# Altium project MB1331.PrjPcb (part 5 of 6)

## Sheet STLink_V3E_SWD.SchDoc: ST-LINK V3 SWD Module
size A3; Date: Not used; ApprovedBy: Not used; CheckedBy: Not used; Author: Not used; CompanyName: STMicroelectronics; DrawnBy: Not used; Engineer: Not used; Organization: Not used; Address1: Not used; Address2: Not used; Address3: Not used; Address4: Not used; DocumentNumber: Not used; Revision: Not used; SheetNumber: 23; SheetTotal: 23
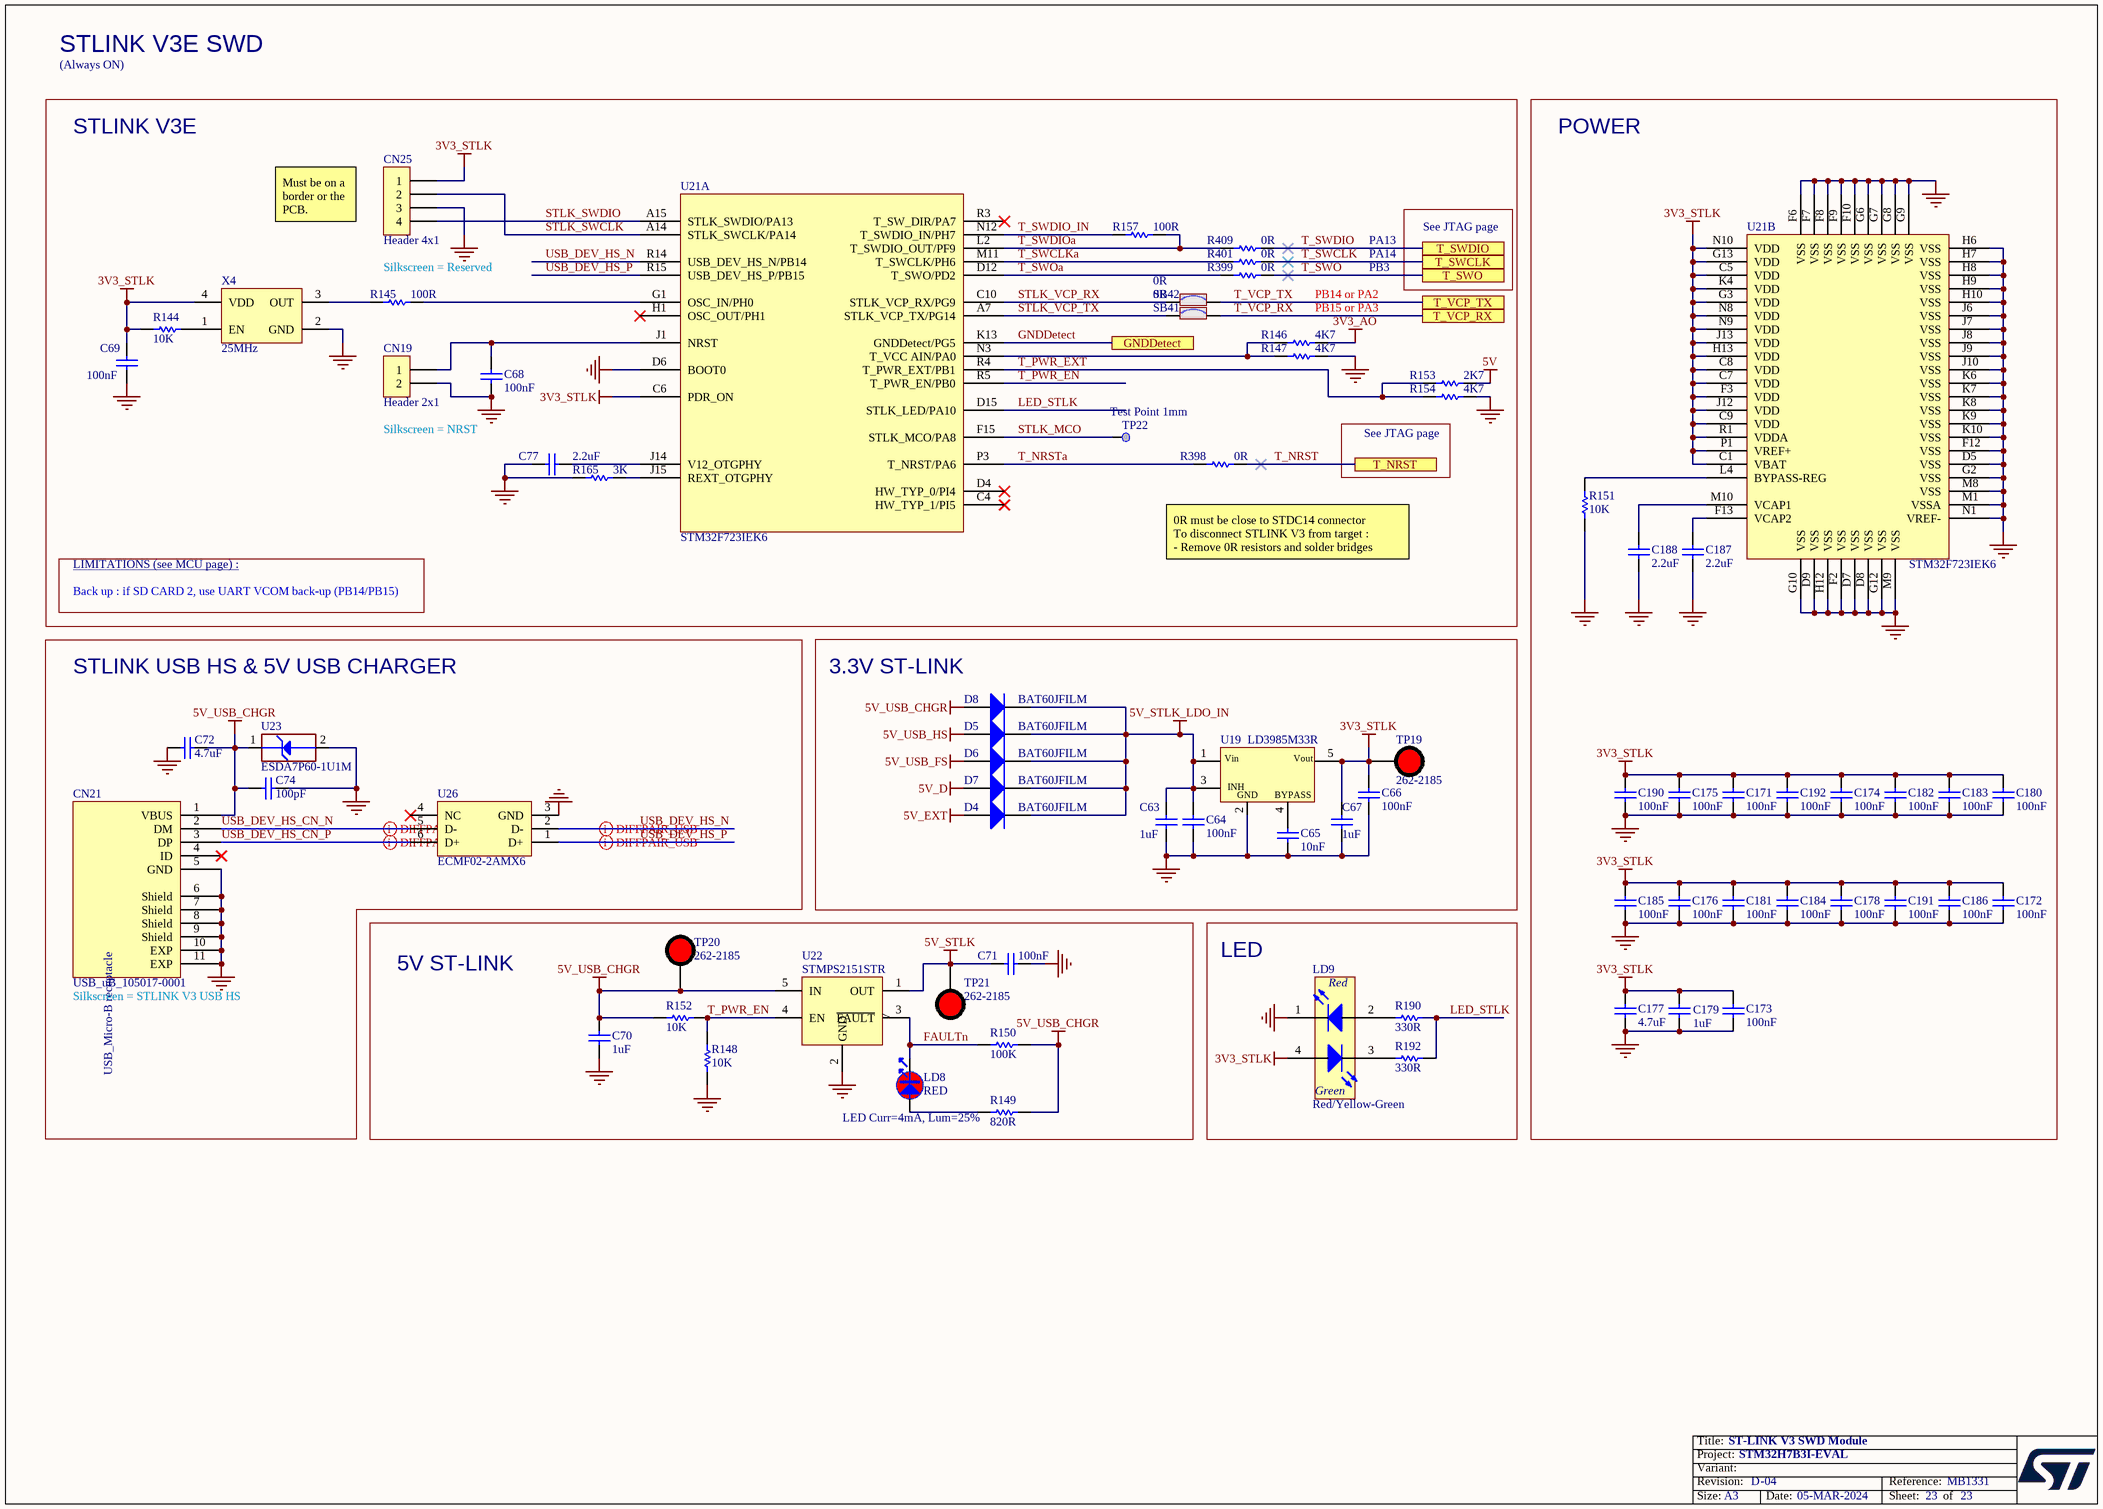
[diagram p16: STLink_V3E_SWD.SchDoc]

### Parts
C63  value 1uF  [C0603]  (hidden comment: Capacitor)
C64  value 100nF  [C0402]  (hidden comment: Capacitor)
C65  value 10nF  [C0402]  (hidden comment: Capacitor)
C66  value 100nF  [C0603]  (hidden comment: Capacitor)
C67  value 1uF  [C0603]  (hidden comment: Capacitor)
C68  value 100nF  [C0402]  (hidden comment: Capacitor)
C69  value 100nF  [C0402]  (hidden comment: Capacitor)
C70  value 1uF  [C0603]  (hidden comment: Capacitor)
C71  value 100nF  [C0402]  (hidden comment: Capacitor)
C72  value 4.7uF  [C0603]  (hidden comment: Capacitor)
C74  value 100pF  [C0402]  (hidden comment: Capacitor)
C77  value 2.2uF  [C0603]  (hidden comment: Capacitor)
C171  value 100nF  [C0402]  (hidden comment: Capacitor)
C172  value 100nF  [C0402]  (hidden comment: Capacitor)
C173  value 100nF  [C0402]  (hidden comment: Capacitor)
C174  value 100nF  [C0402]  (hidden comment: Capacitor)
C175  value 100nF  [C0402]  (hidden comment: Capacitor)
C176  value 100nF  [C0402]  (hidden comment: Capacitor)
C177  value 4.7uF  [C0603]  (hidden comment: Capacitor)
C178  value 100nF  [C0402]  (hidden comment: Capacitor)
C179  value 1uF  [C0603]  (hidden comment: Capacitor)
C180  value 100nF  [C0402]  (hidden comment: Capacitor)
C181  value 100nF  [C0402]  (hidden comment: Capacitor)
C182  value 100nF  [C0402]  (hidden comment: Capacitor)
C183  value 100nF  [C0402]  (hidden comment: Capacitor)
C184  value 100nF  [C0402]  (hidden comment: Capacitor)
C185  value 100nF  [C0402]  (hidden comment: Capacitor)
C186  value 100nF  [C0402]  (hidden comment: Capacitor)
C187  value 2.2uF  [C0603]  (hidden comment: Capacitor)
C188  value 2.2uF  [C0603]  (hidden comment: Capacitor)
C190  value 100nF  [C0402]  (hidden comment: Capacitor)
C191  value 100nF  [C0402]  (hidden comment: Capacitor)
C192  value 100nF  [C0402]  (hidden comment: Capacitor)
CN19  Header 2x1  [CON_SAMTEC_TSW-102-07-G-S]
CN21  value USB_uB_105017-0001  [CON_USBMICROB_MOLEX_105017-0001_H2P90]  (hidden comment: USB_uB_105017.0001)
CN25  Header 4x1  [CON_SAMTEC_TSW-104-07-G-S]
D4  BAT60JFILM  [DIO_SOD323]
D5  BAT60JFILM  [DIO_SOD323]
D6  BAT60JFILM  [DIO_SOD323]
D7  BAT60JFILM  [DIO_SOD323]
D8  BAT60JFILM  [DIO_SOD323]
LD8  value RED  [LED_0603_VISHAY_VLMS1300-GS08_RED_1A2K_H0P8]  (hidden comment: LED_red)
LD9  value Red/Yellow-Green  [LED_BI-GR_HSMF-A201-A00J1]  (hidden comment: LD_BICOLOR_CMS)
R144  value 10K  [R0402]  (hidden comment: Resistor)
R145  value 100R  [R0402]  (hidden comment: Resistor)
R146  value 4K7  [R0402]  (hidden comment: Resistor)
R147  value 4K7  [R0402]  (hidden comment: Resistor)
R148  value 10K  [R0402]  (hidden comment: Resistor)
R149  value 820R  [R0402]  (hidden comment: Resistor)
R150  value 100K  [R0402]  (hidden comment: Resistor)
R151  value 10K  [R0402]  (hidden comment: Resistor)
R152  value 10K  [R0402]  (hidden comment: Resistor)
R153  value 2K7  [R0402]  (hidden comment: Resistor)
R154  value 4K7  [R0402]  (hidden comment: Resistor)
R157  value 100R  [R0402]  (hidden comment: Resistor)
R165  value 3K  [R0402]  (hidden comment: Resistor)
R190  value 330R  [R0603]  (hidden comment: Resistor)
R192  value 330R  [R0603]  (hidden comment: Resistor)
R398  value 0R  [R0402]  (hidden comment: Resistor)
R399  value 0R  [R0402]  (hidden comment: Resistor)
R401  value 0R  [R0402]  (hidden comment: Resistor)
R409  value 0R  [R0402]  (hidden comment: Resistor)
SB41  value 0R  [SOLDER-BRIDGE_R0402-0R]  (hidden comment: SB_ON)
SB42  value 0R  [SOLDER-BRIDGE_R0402-0R]  (hidden comment: SB_ON)
TP19  value 262-2185  [TP_PTH-1MM_TEST-TERMINAL_RS_262-2185_RED]  (hidden comment: Test_pin_conn_red)
TP20  value 262-2185  [TP_PTH-1MM_TEST-TERMINAL_RS_262-2185_RED]  (hidden comment: Test_pin_conn_red)
TP21  value 262-2185  [TP_PTH-1MM_TEST-TERMINAL_RS_262-2185_RED]  (hidden comment: Test_pin_conn_red)
TP22  value Test Point 1mm  [TP_SMD_1MM]  (hidden comment: Test Point)  (no BOM)
U19  LD3985M33R  [REG_SOT23-5L]
U21  value STM32F723IEK6  [ICC_UFBGA201_176+25_10X10_P065]  (hidden comment: ST-LINKV3E_SWD)  (parts A,B of 2)
U22  STMPS2151STR  [MOS_SOT23-5L]
U23  value ESDA7P60-1U1M  [ESD_QFN2_1P6X1_P125]  (hidden comment: ESD-TRANSIL)
U26  ECMF02-2AMX6  [ESD_QFN-6L_1P7X1P5_P050]
X4  value 25MHz  [OSC_NDK_NZ2520SB_4P]  (hidden comment: OSCILLATOR_4_PINS)

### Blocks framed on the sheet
STLINK V3E: C68 C69 C77 CN19 CN25 R144-R147 R153 R154 R157 R165 R398 R399 R401 R409 SB41 SB42 TP22 U21 X4
POWER: C171-C188 C190-C192 R151 U21
STLINK USB HS & 5V USB CHARGER: C72 C74 CN21 U23 U26
3.3V ST-LINK: C63-C67 D4-D8 TP19 U19
5V ST-LINK: C70 C71 LD8 R148-R150 R152 TP20 TP21 U22
LED: LD9 R190 R192

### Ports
GNDDetect, T_NRST, T_SWCLK, T_SWDIO, T_SWO, T_VCP_RX, T_VCP_TX

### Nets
3V3_AO: R146.2
3V3_STLK: C66.2 C67.2 C69.2 C171.2 C172.2 C173.2 C174.2 C175.2 C176.2 C177.2 C178.2 C179.2 C180.2 C181.2 C182.2 C183.2 C184.2 C185.2 C186.2 C190.2 C191.2 C192.2 CN25.1 LD9.4(YellowGreen_anode) R144.1 TP19.1 U19.5(Vout) U21.C1(VBAT) U21.C5(VDD) U21.C6(PDR_ON) U21.C7(VDD) U21.C8(VDD) U21.C9(VDD) U21.F3(VDD) U21.G3(VDD) U21.G13(VDD) U21.H13(VDD) U21.J12(VDD) U21.J13(VDD) U21.K4(VDD) U21.N8(VDD) U21.N9(VDD) U21.N10(VDD) U21.P1(VREF+) U21.R1(VDDA) X4.4(VDD)
5V: R153.2
5V_D: D7.1(A)
5V_EXT: D4.1(A)
5V_STLK: C71.2 TP21.1 U22.1(OUT)
5V_STLK_LDO_IN: C63.1 C64.2 D4.2(K) D5.2(K) D6.2(K) D7.2(K) D8.2(K) U19.1(Vin) U19.3(CE)
5V_USB_CHGR: C70.2 C72.1 C74.1 CN21.1(VBUS) D8.1(A) R149.2 R150.2 R152.2 TP20.1 U22.5(IN) U23.1(IO1)
5V_USB_FS: D6.1(A)
5V_USB_HS: D5.1(A)
GND: C63.2 C64.1 C65.1 C66.1 C67.1 C68.1 C69.1 C70.1 C71.1 C72.2 C74.2 C77.1 C171.1 C172.1 C173.1 C174.1 C175.1 C176.1 C177.1 C178.1 C179.1 C180.1 C181.1 C182.1 C183.1 C184.1 C185.1 C186.1 C187.1 C188.1 C190.1 C191.1 C192.1 CN19.2 CN21.5(GND) CN21.6(Shield) CN21.7(Shield) CN21.8(Shield) CN21.9(Shield) CN21.10(EXP) CN21.11(EXP) CN25.3 LD9.1(RED_cathode) R147.2 R148.2 R151.1 R154.1 R165.1 U19.2(GND) U21.D5(VSS) U21.D6(BOOT0) U21.D7(VSS) U21.D8(VSS) U21.D9(VSS) U21.F2(VSS) U21.F6(VSS) U21.F7(VSS) U21.F8(VSS) U21.F9(VSS) U21.F10(VSS) U21.F12(VSS) U21.G2(VSS) U21.G6(VSS) U21.G7(VSS) U21.G8(VSS) U21.G9(VSS) U21.G10(VSS) U21.G12(VSS) U21.H6(VSS) U21.H7(VSS) U21.H8(VSS) U21.H9(VSS) U21.H10(VSS) U21.H12(VSS) U21.J6(VSS) U21.J7(VSS) U21.J8(VSS) U21.J9(VSS) U21.J10(VSS) U21.K6(VSS) U21.K7(VSS) U21.K8(VSS) U21.K9(VSS) U21.K10(VSS) U21.M1(VSSA) U21.M8(VSS) U21.M9(VSS) U21.N1(VREF-) U22.2(GND) U23.2(GND) U26.3(GND) X4.2(GND)
FAULTn: LD8.2 R150.1 U22.3(~{FAULT})
GNDDetect: U21.K13(GNDDetect/PG5) ; port GNDDetect
LED_STLK: R190.2 R192.2 U21.D15(STLK_LED/PA10)
STLK_MCO: TP22.1 U21.F15(STLK_MCO/PA8)
STLK_SWCLK: CN25.2 U21.A14(STLK_SWCLK/PA14)
STLK_SWDIO: CN25.4 U21.A15(STLK_SWDIO/PA13)
STLK_VCP_RX: SB42.1 U21.C10(STLK_VCP_RX/PG9)
STLK_VCP_TX: SB41.1 U21.A7(STLK_VCP_TX/PG14)
T_NRST: R398.2 ; port T_NRST  [project net JTAG_HOST_NRST]
T_NRSTa: R398.1 U21.P3(T_NRST/PA6)
T_PWR_EN: R148.1 R152.1 U21.R5(T_PWR_EN/PB0) U22.4(EN)
T_PWR_EXT: R153.1 R154.2 U21.R4(T_PWR_EXT/PB1)
T_SWCLK: R401.2 ; port T_SWCLK  [project net JTAG_TCK]
T_SWCLKa: R401.1 U21.M11(T_SWCLK/PH6)
T_SWDIO: R409.2 ; port T_SWDIO  [project net JTAG_TMS]
T_SWDIO_IN: R157.1 U21.N12(T_SWDIO_IN/PH7)
T_SWDIOa: R157.2 R409.1 U21.L2(T_SWDIO_OUT/PF9)
T_SWO: R399.2 ; port T_SWO  [project net JTAG_TDO]
T_SWOa: R399.1 U21.D12(T_SWO/PD2)
T_VCP_RX: SB41.2 ; port T_VCP_RX
T_VCP_TX: SB42.2 ; port T_VCP_TX
USB_DEV_HS_CN_N: CN21.2(DM) U26.5(D-)
USB_DEV_HS_CN_P: CN21.3(DP) U26.6(D+)
USB_DEV_HS_N: U21.R14(USB_DEV_HS_N/PB14) U26.2(D-)
USB_DEV_HS_P: U21.R15(USB_DEV_HS_P/PB15) U26.1(D+)
NetC65_2: C65.2 U19.4(BYPASS)
NetC68_2: C68.2 CN19.1 U21.J1(NRST)
NetC77_2: C77.2 U21.J14(V12_OTGPHY)
NetC187_2: C187.2 U21.F13(VCAP2)
NetC188_2: C188.2 U21.M10(VCAP1)
NetLD8_1: LD8.1 R149.1
NetLD9_2: LD9.2(Red_anode) R190.1
NetLD9_3: LD9.3(YellowGreen_cathode) R192.1
NetR144_2: R144.2 X4.1(EN)
NetR145_1: R145.1 X4.3(OUT)
NetR145_2: R145.2 U21.G1(OSC_IN/PH0)
NetR146_1: R146.1 R147.1 U21.N3(T_VCC_AIN/PA0)
NetR151_2: R151.2 U21.L4(BYPASS-REG)
NetR165_2: R165.2 U21.J15(REXT_OTGPHY)

Not connected (* = marked no-connect by the designer): CN21 4(ID)*; U21 C4(HW_TYP_1/PI5)* D4(HW_TYP_0/PI4)* H1(OSC_OUT/PH1)* R3(T_SW_DIR/PA7)*; U26 4(NC)*

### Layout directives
differential pair; rule Impedance Constraint [Min = 85.00    Max = 95.00    ]: USB_DEV_HS_CN_N, USB_DEV_HS_CN_P, USB_DEV_HS_N, USB_DEV_HS_P

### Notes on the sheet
- STLINK V3E SWD
- (Always ON)
- Must be on a border or the PCB.
- PA13
- See JTAG page
- Silkscreen = Reserved
- PB14 or PA2
- PB15 or PA3
- PA14
- PB3
- Silkscreen = NRST
- LIMITATIONS (see MCU page) :
- (near R398) 0R must be close to STDC14 connector
  To disconnect STLINK V3 from target :
  - Remove 0R resistors and solder bridges
- Back up : if SD CARD 2, use UART VCOM back-up (PB14/PB15)
- (near CN21) Silkscreen = STLINK V3 USB HS
- LED Curr=4mA, Lum=25%

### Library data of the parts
C63 = MCD-00238: Capacitor, MLCC, 1uF, 6V3, X5R, 10%, 0603, T=0,8mm; Manufacturer_Part_Number: CC0603KRX5R5BB105; Manufacturer: YAGEO; Part_Preference: Recommended; Provided_By: SUBCO; ECCN_US: EAR99; ECCN_EU: NEC; Component_Country_Of_Origin: China; ID: 2629; ShowFields: YES
C64 C68 C69 C71 C171-C176 C178 C180-C186 C190-C192 = MCD-00006: Capacitor, MLCC, 100nF, 16V, X7R, 10%, 0402, T=0.5mm; Manufacturer_Part_Number: CC0402KRX7R7BB104; Manufacturer: YAGEO; Alternate_Manufacturer_Part_Number: GCM155R71C104KA55D; Alternate_Manufacturer: MURATA; Part_Preference: Recommended; Partial_Alternate_Internal_Part_Number: MCD-03299; Provided_By: SUBCO; ECCN_US: EAR99; ECCN_EU: NEC; Component_Country_Of_Origin: China; ID: 2474; Order_Code_RS: 9402047; ShowFields: YES
C65 = MCD-00011: Capacitor, MLCC, 10nF, 16V, X7R, 10%, 0402, T=0.5mm; Manufacturer_Part_Number: CC0402KRX7R7BB103; Manufacturer: YAGEO; Part_Preference: Recommended; Provided_By: SUBCO; ECCN_US: EAR99; ECCN_EU: NEC; Component_Country_Of_Origin: China; ID: 2469; Order_Code_RS: 3019275; ShowFields: YES
C66 = MCD-00211: Capacitor, MLCC, 100nF, 16V, X7R, 10%, 0603, T=0,8mm; Manufacturer_Part_Number: CC0603KRX7R7BB104; Manufacturer: YAGEO; Part_Preference: Recommended; Partial_Alternate_Internal_Part_Number: MCD-01099; Provided_By: SUBCO; ECCN_US: EAR99; ECCN_EU: NEC; Component_Country_Of_Origin: China; ID: 2659; Order_Code_RS: 669-8763; ShowFields: YES
C67 C70 C179 = MCD-00010: Capacitor, MLCC, 1uF, 16V, X5R, 10%, 0603, T=0,8mm; Manufacturer_Part_Number: CC0603KRX5R7BB105; Manufacturer: YAGEO; Part_Preference: Recommended; Provided_By: SUBCO; ECCN_US: EAR99; ECCN_EU: NEC; Component_Country_Of_Origin: China; ID: 2470; Order_Code_RS: 2370680; ShowFields: YES
C72 C177 = MCD-00009: Capacitor, MLCC, 4.7uF, 16V, X5R, 10%, 0603, T=0.8mm; Manufacturer_Part_Number: CC0603KRX5R7BB475; Manufacturer: YAGEO; Part_Preference: Recommended; Partial_Alternate_Internal_Part_Number: MCD-03565; Provided_By: SUBCO; ECCN_US: EAR99; ECCN_EU: NEC; Alternate_EMS: A; Component_Country_Of_Origin: China; ID: 2471; ShowFields: YES
C74 = MCD-00205: Capacitor, MLCC, 100pF, 50V, NPO, 5%, 0402, T=0,5mm; Manufacturer_Part_Number: CC0402JRNPO9BN101; Manufacturer: YAGEO; Part_Preference: Recommended; Provided_By: SUBCO; ECCN_US: EAR99; ECCN_EU: NEC; Component_Country_Of_Origin: China; ID: 2658; ShowFields: YES
C77 C187 C188 = MCD-00012: Capacitor, MLCC, 2.2uF, 10V, X5R, 10%, 0603, T=0,8mm; Manufacturer_Part_Number: CC0603KRX5R6BB225; Manufacturer: YAGEO; Alternate_Manufacturer_Part_Number: C0603C225K8PACTU; Alternate_Manufacturer: KEMET; BMS_Part_Number: 9142010; Part_Preference: Recommended; Partial_Alternate_Internal_Part_Number: MCD-00551; Provided_By: SUBCO; ECCN_US: EAR99; ECCN_EU: NEC; Component_Country_Of_Origin: China; ID: 2467; Order_Code_RS: 2370679; ShowFields: YES
CN19 = MCD-00032: Header, 2x1, 2,54mm, VR, TH, Height 5.84mm/2.54mm; Part_Type: Connector; Manufacturer_Part_Number: TSW-102-07-G-S; Manufacturer: SAMTEC; Alternate_Manufacturer_Part_Number: 313102S111116; Alternate_Manufacturer: JIUBABA; Part_Preference: Recommended; Provided_By: SUBCO; Component_Country_Of_Origin: China, Costa Rica, Malaysia, USA, Vietnam; ID: 2484; Order_Code_RS: 2505044; ShowFields: YES
CN21 = MCD-00028: USB-MICRO-B, 0.65mm, RA, SMT, Bottom Mount,; Manufacturer_Part_Number: 1050170001; Manufacturer: MOLEX; Part_Type: Connector; Part_Preference: Recommended; Provided_By: SUBCO; Component_Country_Of_Origin: Unknown; ID: 2489; Order_Code_RS: 2293836; ShowFields: YES
CN25 = MCD-00029: Header, 4x1, 2,54mm, VR, TH, Height 5.84mm/2.54mm; Manufacturer_Part_Number: TSW-104-07-G-S; Manufacturer: SAMTEC; Part_Type: Connector; Part_Preference: Recommended; Provided_By: SUBCO; Component_Country_Of_Origin: China, Costa Rica, Malaysia, USA, Vietnam; ID: 2487; Order_Code_RS: 2667450; ShowFields: YES
D4-D8 = MCD-00034: Manufacturer: STMICROELECTRONICS; Part_Type: Diode; BMS_Part_Number: 9151097; Manufacturer_HQ_COO: EU; Part_Preference: Recommended; Provided_By: SUBCO with ST control; ECCN_US: EAR99; ECCN_EU: NEC; Component_Country_Of_Origin: China; ID: 2483; Order_Code_RS: 714-6879; ShowFields: YES
LD8 = MCD-00587: LED Red, 0603 SMD, 2V Forward Voltage; Part_Type: Display; Manufacturer_Part_Number: VLMS1300-GS08; Manufacturer: VISHAY; Alternate_Manufacturer_Part_Number: LS Q976-NR-1; Alternate_Manufacturer: OSRAM OPTO SEMICONDUCTORS; Full_Alternate_Internal_Part_Number: MCD-02401; Part_Preference: Recommended; Provided_By: SUBCO; Component_Country_Of_Origin: China; ID: 3154; ShowFields: YES
LD9 = MCD-02402: LED Bicolor, Red/Yellow-Green , 2V, 20mA, 4-PLCC; Part_Type: Display; Manufacturer_Part_Number: 67-22SURSYGC/S530-A2/TR8; Manufacturer: EVERLIGHT; Part_Preference: Not recommended; Full_Alternate_Internal_Part_Number: MCD-00051, MCD-02631; ShowFields: YES; ID: 4508
R144 R148 R151 R152 = MCD-00053: Resistor,10K,0402,1%,1/16W; Manufacturer_Part_Number: RC0402FR-0710KL; Manufacturer: YAGEO; BMS_Part_Number: 9131590; Part_Preference: Recommended; Provided_By: SUBCO; ECCN_US: EAR99; ECCN_EU: NEC; Component_Country_Of_Origin: China; ID: 2539; Order_Code_RS: 9239359; ShowFields: YES
R145 R157 = MCD-00067: Resistor,100R,0402,1%,1/16W; Manufacturer_Part_Number: RC0402FR-07100RL; Manufacturer: YAGEO; Part_Preference: Recommended; Provided_By: SUBCO; ECCN_US: EAR99; ECCN_EU: NEC; Component_Country_Of_Origin: China; ID: 2527; Order_Code_RS: 9239111; ShowFields: YES
R146 R147 R154 = MCD-00065: Resistor,4K7,0402,1%,1/16W; Manufacturer_Part_Number: RC0402FR-074K7L; Manufacturer: YAGEO; Alternate_Manufacturer_Part_Number: RT0402FRE074K7L; Part_Preference: Recommended; Partial_Alternate_Internal_Part_Number: MCD-03300; Provided_By: SUBCO; ECCN_US: EAR99; ECCN_EU: NEC; Component_Country_Of_Origin: China; ID: 2526; Order_Code_RS: 9239316; ShowFields: YES
R149 = MCD-00527: Resistor,820R,0402,1%,1/16W; Manufacturer_Part_Number: RC0402FR-07820RL; Manufacturer: YAGEO; Part_Preference: Recommended; Provided_By: SUBCO; ECCN_US: EAR99; ECCN_EU: NEC; Component_Country_Of_Origin: China; ID: 3217; ShowFields: YES
R150 = MCD-00059: Resistor,100K,0402,1%,1/16W; Manufacturer_Part_Number: RC0402FR-07100KL; Manufacturer: YAGEO; Alternate_Manufacturer_Part_Number: RT0402FRE07100KL; Part_Preference: Recommended; Partial_Alternate_Internal_Part_Number: MCD-03301; Provided_By: SUBCO; ECCN_US: EAR99; ECCN_EU: NEC; Component_Country_Of_Origin: China; ID: 2533; Order_Code_RS: 2421891; ShowFields: YES
R153 = MCD-00055: Resistor,2K7,0402,1%,1/16W; Manufacturer_Part_Number: RC0402FR-072K7L; Manufacturer: YAGEO; Part_Preference: Recommended; Provided_By: SUBCO; ECCN_US: EAR99; ECCN_EU: NEC; Component_Country_Of_Origin: China; ID: 2535; Order_Code_RS: 9239286; ShowFields: YES
R165 = MCD-00185: Resistor,3K,0402,1%,1/16W; Manufacturer_Part_Number: RC0402FR-073KL; Manufacturer: YAGEO; Part_Preference: Recommended; Provided_By: SUBCO; ECCN_US: EAR99; ECCN_EU: NEC; Component_Country_Of_Origin: China; ID: 2682; ShowFields: YES
R190 R192 = MCD-00197: Resistor,330R,0603,1%,1/10W; Manufacturer_Part_Number: RC0603FR-07330RL; Manufacturer: YAGEO; BMS_Part_Number: 9129729; Part_Preference: Recommended; Provided_By: SUBCO; ECCN_US: EAR99; ECCN_EU: NEC; Component_Country_Of_Origin: China; ID: 2672; ShowFields: YES
R398 R399 R401 R409 = MCD-00052: Resistor,0R,0402,5%,1/16W; Manufacturer_Part_Number: RC0402JR-070RL; Manufacturer: YAGEO; Part_Preference: Recommended; Provided_By: SUBCO; ECCN_US: EAR99; ECCN_EU: NEC; Component_Country_Of_Origin: China; ID: 2540; Order_Code_RS: 9232516RL; ShowFields: YES
SB41 SB42 = MCD-01618: Solder Bridge 0402 ON; Part_Type: Resistor; Manufacturer_Part_Number: RC0402JR-070RL; Manufacturer: YAGEO; Part_Preference: Recommended; Provided_By: SUBCO; Component_Country_Of_Origin: China; ID: 3718; Order_Code_RS: 618-5804; ShowFields: YES
TP19-TP21 = MCD-00712: RS Pro 1mm Red Test Terminal; Part_Type: Misc; Manufacturer: RS PRO; Part_Preference: Recommended; Provided_By: SUBCO; Component_Country_Of_Origin: UK; ID: 3035; ShowFields: YES
TP22 = MCD-00074: Test Point 1mm; Part_Type: Misc; Part_Preference: Recommended; Component_Country_Of_Origin: Unknown; ID: 2518; ShowFields: YES
U19 = MCD-00086: Ultra low drop-low noise BiCMOS voltage, regulators low ESR capacitors compatible; Manufacturer: STMICROELECTRONICS; Part_Type: IC; BMS_Part_Number: 9176161; Manufacturer_HQ_COO: EU; Part_Preference: Recommended; Provided_By: SUBCO with ST control; ECCN_US: EAR99; ECCN_EU: NEC; Component_Country_Of_Origin: China; ID: 2506; Order_Code_RS: 168-6500; ShowFields: YES
U21 = MCD-00596: STM32F723IEK  (STM32F7) BGA176; Part_Type: IC; Manufacturer: STMICROELECTRONICS; BMS_Part_Number: 9175300; Manufacturer_HQ_COO: EU; Part_Preference: Recommended; Provided_By: SUBCO with ST control; ECCN_US: 3A991A2; ECCN_EU: NEC; Component_Country_Of_Origin: Philippines; ID: 3144; Order_Code_RS: 135-8268; ShowFields: YES
U22 = MCD-00159: 500mA, Enhanced single channel power switches with active high enable pin; Part_Type: IC; Manufacturer: STMICROELECTRONICS; Alternate_Manufacturer_Part_Number: TPS2051C; Alternate_Manufacturer: TEXAS INSTRUMENTS; BMS_Part_Number: 9159009; Part_Preference: Recommended; Provided_By: SUBCO with ST control; ECCN_US: EAR99; ECCN_EU: NEC; Component_Country_Of_Origin: Malaysia; ID: 2708; Order_Code_RS: 165-5516; ShowFields: YES
U23 = MCD-00251: High power transient voltage suppressor, 7V breakdown; Part_Type: Diode; Manufacturer: STMICROELECTRONICS; BMS_Part_Number: 9179042; Manufacturer_HQ_COO: EU; Part_Preference: Recommended; Provided_By: SUBCO with ST control; ECCN_US: EAR99; ECCN_EU: NEC; Component_Country_Of_Origin: China; ID: 2618; Order_Code_RS: 110-6381; ShowFields: YES
U26 = MCD-00649: Common mode filter with ESD protection for USB 2.0 interface; Part_Type: Diode; Manufacturer: STMICROELECTRONICS; BMS_Part_Number: 9151138; Manufacturer_HQ_COO: EU; Part_Preference: Recommended; Provided_By: SUBCO with ST control; ECCN_US: EAR99; ECCN_EU: NEC; Component_Country_Of_Origin: China; ID: 3094; Order_Code_RS: 880-5276; ShowFields: YES
X4 = MCD-00597: Oscillator 25Mhz, +-50ppm, Vcc:3.3V typ, square wave: [0.1Vcc;0.9Vcc], Enable pin, SMD; Part_Type: Crystal_Osc; Manufacturer_Part_Number: NZ2520SH-25MHZ-END4869C; Manufacturer: NDK; Alternate_Manufacturer_Part_Number: NZ2520SB 25MHz END4869B; BMS_Part_Number: 9157050; Part_Preference: Recommended; Provided_By: SUBCO; ECCN_US: EAR99; ECCN_EU: NEC; Component_Country_Of_Origin: Unknown; ID: 3148; ShowFields: YES

## Sheet ExtensionConnector.SchDoc: Extension Connectors
size A4; Date: Not used; ApprovedBy: Not used; CheckedBy: Not used; Author: Not used; CompanyName: STMicroelectronics; DrawnBy: Not used; Engineer: Not used; Organization: Not used; Address1: Not used; Address2: Not used; Address3: Not used; Address4: Not used; DocumentNumber: Not used; Revision: Not used; SheetNumber: 19; SheetTotal: 23
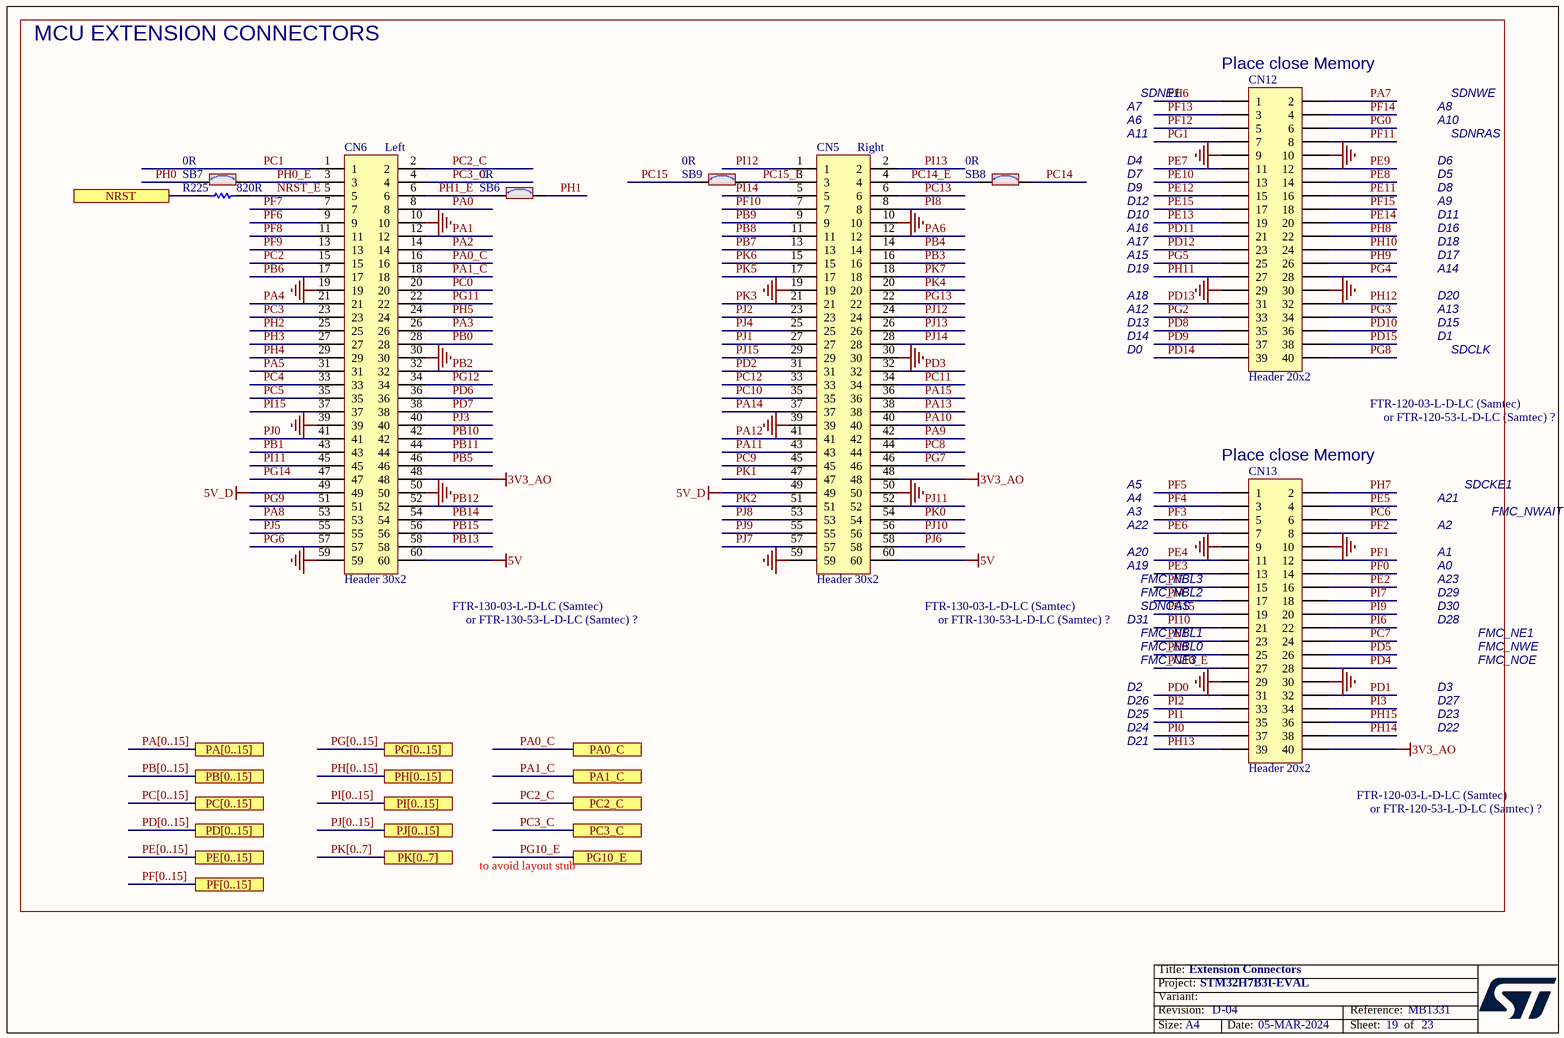
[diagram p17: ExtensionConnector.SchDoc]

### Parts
CN5  Header 30x2  [CON_SAMTEC_FTR-130-53-L-D-LC]
CN6  Header 30x2  [CON_SAMTEC_FTR-130-53-L-D-LC]
CN12  Header 20x2  [CON_SAMTEC_FTR-120-53-L-D-LC]
CN13  Header 20x2  [CON_SAMTEC_FTR-120-53-L-D-LC]
R225  value 820R  [R0603]  (hidden comment: Resistor)
SB6  value 0R  [SOLDER-BRIDGE_R0603-0R]  (hidden comment: SB_ON)
SB7  value 0R  [SOLDER-BRIDGE_R0603-0R]  (hidden comment: SB_ON)
SB8  value 0R  [SOLDER-BRIDGE_R0603-0R]  (hidden comment: SB_ON)
SB9  value 0R  [SOLDER-BRIDGE_R0603-0R]  (hidden comment: SB_ON)

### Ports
NRST, PA0_C, PA1_C, PA[0..15], PB[0..15], PC2_C, PC3_C, PC[0..15], PD[0..15], PE[0..15], PF[0..15], PG10_E, PG[0..15], PH[0..15], PI[0..15], PJ[0..15], PK[0..7]

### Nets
3V3_AO: CN5.48 CN6.48 CN13.40
5V: CN5.60 CN6.60
5V_D: CN5.49 CN6.49
GND: CN5.10 CN5.19 CN5.30 CN5.39 CN5.50 CN5.59 CN6.10 CN6.19 CN6.30 CN6.39 CN6.50 CN6.59 CN12.9 CN12.10 CN12.29 CN12.30 CN13.9 CN13.10 CN13.29 CN13.30
NRST: R225.1 ; port NRST
NRST_E: CN6.5 R225.2
PA0: CN6.8
PA0_C: CN6.16 ; port PA0_C
PA1: CN6.12
PA1_C: CN6.18 ; port PA1_C
PA2: CN6.14
PA3: CN6.26
PA4: CN6.21
PA5: CN6.31
PA6: CN5.12
PA7: CN12.2
PA8: CN6.53
PA9: CN5.42
PA10: CN5.40
PA11: CN5.43
PA12: CN5.41
PA13: CN5.38
PA14: CN5.37
PA15: CN5.36
PB0: CN6.28
PB1: CN6.43
PB2: CN6.32
PB3: CN5.16
PB4: CN5.14
PB5: CN6.46
PB6: CN6.17  [project net DFSDM1_DATIN5]
PB7: CN5.13
PB8: CN5.11
PB9: CN5.9
PB10: CN6.42
PB11: CN6.44
PB12: CN6.52
PB13: CN6.58
PB14: CN6.54
PB15: CN6.56
PC0: CN6.20
PC1: CN6.1
PC2: CN6.15
PC2_C: CN6.2 ; port PC2_C
PC3: CN6.23
PC3_C: CN6.4 ; port PC3_C
PC4: CN6.33
PC5: CN6.35
PC6: CN13.6
PC7: CN13.24
PC8: CN5.44
PC9: CN5.45
PC10: CN5.35
PC11: CN5.34
PC12: CN5.33
PC13: CN5.6
PC14: SB8.2
PC14_E: CN5.4 SB8.1
PC15: SB9.1
PC15_E: CN5.3 SB9.2
PD0: CN13.31
PD1: CN13.32
PD2: CN5.31
PD3: CN5.32
PD4: CN13.28
PD5: CN13.26
PD6: CN6.36
PD7: CN6.38
PD8: CN12.35
PD9: CN12.37
PD10: CN12.36
PD11: CN12.21
PD12: CN12.23
PD13: CN12.31
PD14: CN12.39
PD15: CN12.38
PE0: CN13.25
PE1: CN13.23
PE2: CN13.16
PE3: CN13.13
PE4: CN13.11
PE5: CN13.4
PE6: CN13.7
PE7: CN12.11
PE8: CN12.14
PE9: CN12.12
PE10: CN12.13
PE11: CN12.16
PE12: CN12.15
PE13: CN12.19
PE14: CN12.20
PE15: CN12.17
PF0: CN13.14
PF1: CN13.12
PF2: CN13.8
PF3: CN13.5
PF4: CN13.3
PF5: CN13.1
PF6: CN6.9
PF7: CN6.7
PF8: CN6.11
PF9: CN6.13
PF10: CN5.7
PF11: CN12.8
PF12: CN12.5
PF13: CN12.3
PF14: CN12.4
PF15: CN12.18
PG0: CN12.6
PG1: CN12.7
PG2: CN12.33
PG3: CN12.34
PG4: CN12.28
PG5: CN12.25
PG6: CN6.57
PG7: CN5.46
PG8: CN12.40
PG9: CN6.51
PG10_E: CN13.27 ; port PG10_E
PG11: CN6.22
PG12: CN6.34
PG13: CN5.22
PG14: CN6.47
PG15: CN13.19
PH0: SB7.1
PH0_E: CN6.3 SB7.2
PH1: SB6.2
PH1_E: CN6.6 SB6.1
PH2: CN6.25  [project net CTP_INT]
PH3: CN6.27
PH4: CN6.29
PH5: CN6.24
PH6: CN12.1
PH7: CN13.2
PH8: CN12.22
PH9: CN12.26
PH10: CN12.24
PH11: CN12.27
PH12: CN12.32
PH13: CN13.39
PH14: CN13.38
PH15: CN13.36
PI0: CN13.37
PI1: CN13.35
PI2: CN13.33
PI3: CN13.34
PI4: CN13.17
PI5: CN13.15
PI6: CN13.22
PI7: CN13.18
PI8: CN5.8
PI9: CN13.20
PI10: CN13.21
PI11: CN6.45
PI12: CN5.1
PI13: CN5.2
PI14: CN5.5
PI15: CN6.37
PJ0: CN6.41
PJ1: CN5.27
PJ2: CN5.23
PJ3: CN6.40
PJ4: CN5.25
PJ5: CN6.55
PJ6: CN5.58
PJ7: CN5.57
PJ8: CN5.53
PJ9: CN5.55
PJ10: CN5.56
PJ11: CN5.52
PJ12: CN5.24
PJ13: CN5.26
PJ14: CN5.28
PJ15: CN5.29
PK0: CN5.54
PK1: CN5.47
PK2: CN5.51
PK3: CN5.21
PK4: CN5.20
PK5: CN5.17
PK6: CN5.15
PK7: CN5.18

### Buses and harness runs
bus PA[0..15] = port PA[0..15]
bus PB[0..15] = port PB[0..15]
bus PC[0..15] = port PC[0..15]
bus PD[0..15] = port PD[0..15]
bus PE[0..15] = port PE[0..15]
bus PF[0..15] = port PF[0..15]
bus PG[0..15] = port PG[0..15]
bus PH[0..15] = port PH[0..15]
bus PI[0..15] = port PI[0..15]
bus PJ[0..15] = port PJ[0..15]
bus PK[0..7] = port PK[0..7]

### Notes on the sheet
- MCU EXTENSION CONNECTORS
- A7
- SDNE1
- (near CN12) Place close Memory
- A8
- SDNWE
- (near CN6) Left
- (near CN5) Right
- D4
- D7
- A6
- A11
- D5
- D6
- A10
- SDNRAS
- A16
- A17
- D9
- D10
- D12
- D8
- D11
- A9
- D16
- D18
- A18
- A12
- A15
- D19
- A13
- A14
- D17
- D20
- D13
- D14
- D0
- D15
- D1
- SDCLK
- (near CN12) FTR-120-03-L-D-LC (Samtec)
- or FTR-120-53-L-D-LC (Samtec) ?
- A3
- A4
- A5
- (near CN13) Place close Memory
- A21
- SDCKE1
- FMC_NWAIT
- A19
- A20
- A22
- FMC_NBL3
- A23
- A0
- A1
- A2
- (near CN6) FTR-130-03-L-D-LC (Samtec)
- or FTR-130-53-L-D-LC (Samtec) ?
- (near CN5) FTR-130-03-L-D-LC (Samtec)
- D31
- FMC_NBL0
- FMC_NBL1
- SDNCAS
- FMC_NBL2
- D28
- D29
- D30
- FMC_NWE
- FMC_NE1
- D2
- D25
- D26
- FMC_NE3
- D3
- D23
- D27
- FMC_NOE
- D21
- D24
- D22
- (near CN13) FTR-120-03-L-D-LC (Samtec)
- to avoid layout stub

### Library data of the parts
CN5 CN6 = MCD-00576: Header 30x2, 1.27mm, VR, CMS, Height 7.24mm; Part_Type: Connector; Manufacturer_Part_Number: FTR-130-53-L-D-LC; Manufacturer: SAMTEC; Alternate_Manufacturer_Part_Number: P1039-2*30MGF-089-1A; Alternate_Manufacturer: JIUBABA; Part_Preference: Recommended; Provided_By: SUBCO; Component_Country_Of_Origin: China, Costa Rica, Malaysia, USA, Vietnam; ID: 3170; ShowFields: YES
CN12 CN13 = MCD-00578: Header 20x2, 1.27mm, VR, CMS, Height 7.24mm; Part_Type: Connector; Manufacturer_Part_Number: FTR-120-53-L-D-LC; Manufacturer: SAMTEC; Alternate_Manufacturer_Part_Number: P1039-2*20MGF-089-1A; Alternate_Manufacturer: JIUBABA; Part_Preference: Recommended; Provided_By: SUBCO; Component_Country_Of_Origin: China, Costa Rica, Malaysia, USA, Vietnam; ID: 3165; ShowFields: YES
R225 = MCD-00528: Resistor,820R,0603,1%,1/10W; Manufacturer_Part_Number: RC0603FR-07820RL; Manufacturer: YAGEO; BMS_Part_Number: 9129759; Part_Preference: Recommended; Provided_By: SUBCO; ECCN_US: EAR99; ECCN_EU: NEC; Component_Country_Of_Origin: China; ID: 3218; ShowFields: YES
SB6-SB9 = MCD-00071: Solder Bridge ON; Part_Type: Resistor; Manufacturer_Part_Number: RC0603JR-070RL; Manufacturer: YAGEO; Manufacturer_HQ_COO: Unknown; Part_Preference: Recommended; Provided_By: SUBCO; Component_Country_Of_Origin: China; ID: 2521; Order_Code_RS: 199-5647; ShowFields: YES

## Sheet USB_OTG_FS.SchDoc: USB_OTG_FS
size A4; Date: Not used; ApprovedBy: Not used; CheckedBy: Not used; Author: Not used; CompanyName: STMicroelectronics; DrawnBy: Not used; Engineer: Not used; Organization: Not used; Address1: Not used; Address2: Not used; Address3: Not used; Address4: Not used; DocumentNumber: Not used; Revision: Not used; SheetNumber: 5; SheetTotal: 23
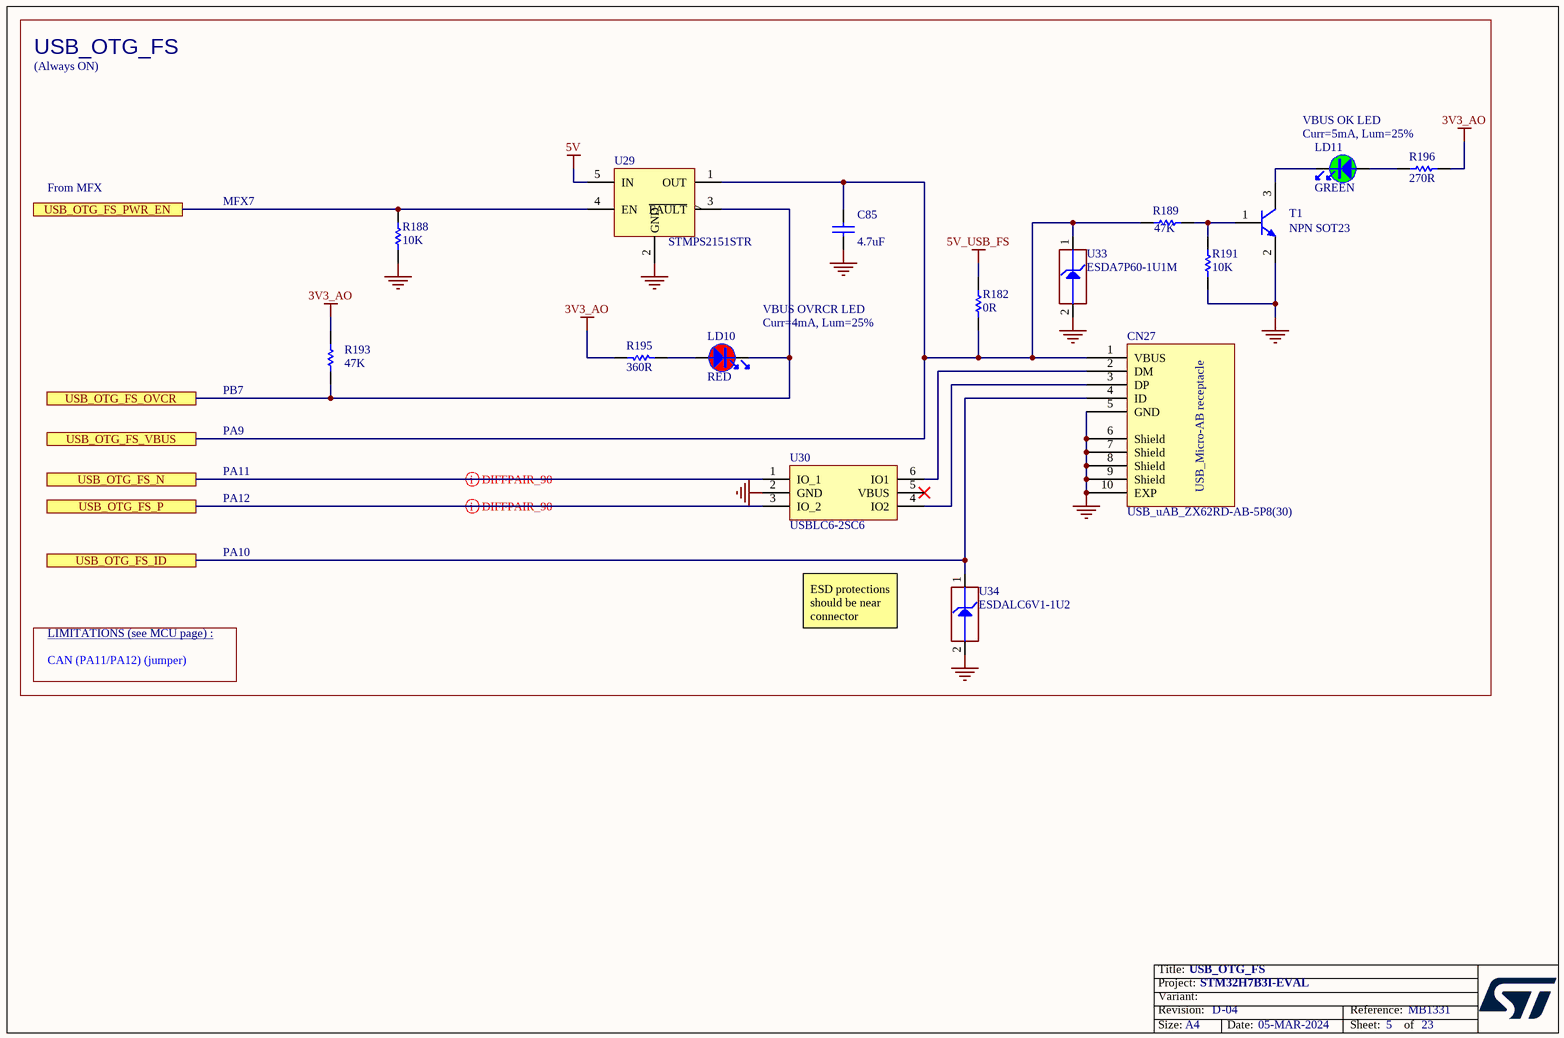
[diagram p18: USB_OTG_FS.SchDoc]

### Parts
C85  value 4.7uF  [C0603]  (hidden comment: Capacitor)
CN27  value USB_uAB_ZX62RD-AB-5P8(30)  [CON_USBMICROAB_MOLEX_47590-0001_H3]  (hidden comment: USB_uAB_47590.0001)
LD10  value RED  [LED_0603_VISHAY_VLMS1300-GS08_RED_1A2K_H0P8]  (hidden comment: LED_red)
LD11  value GREEN  [LED_0603_OSRAM_LG-Q396-PS-35_GREEN_1A2K_H0P4]  (hidden comment: LED_green)
R182  value 0R  [R0805]  (hidden comment: Resistor)
R188  value 10K  [R0402]  (hidden comment: Resistor)
R189  value 47K  [R0402]  (hidden comment: Resistor)
R191  value 10K  [R0402]  (hidden comment: Resistor)
R193  value 47K  [R0402]  (hidden comment: Resistor)
R195  value 360R  [R0402]  (hidden comment: Resistor)
R196  value 270R  [R0402]  (hidden comment: Resistor)
T1  value NPN SOT23  [NPN_SOT23]  (hidden comment: 9013-SOT23)
U29  STMPS2151STR  [MOS_SOT23-5L]
U30  USBLC6-2SC6  [ESD_SOT23-6L]
U33  value ESDA7P60-1U1M  [ESD_QFN2_1P6X1_P125]  (hidden comment: ESD-TRANSIL)
U34  value ESDALC6V1-1U2  [ESD_ST0201]  (hidden comment: ESD-TRANSIL)

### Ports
USB_OTG_FS_ID, USB_OTG_FS_N, USB_OTG_FS_OVCR, USB_OTG_FS_P, USB_OTG_FS_PWR_EN, USB_OTG_FS_VBUS

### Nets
3V3_AO: R193.2 R195.2 R196.2
5V: U29.5(IN)
5V_USB_FS: R182.2
GND: C85.1 CN27.5(GND) CN27.6(Shield) CN27.7(Shield) CN27.8(Shield) CN27.9(Shield) CN27.10(EXP) R188.2 R191.1 T1.2(E) U29.2(GND) U30.2(GND) U33.2(GND) U34.2(GND)
USB_OTG_FS_ID: CN27.4(ID) U34.1(IO1) ; port USB_OTG_FS_ID
USB_OTG_FS_N: U30.1(IO_1) ; port USB_OTG_FS_N
USB_OTG_FS_OVCR: LD10.2 R193.1 U29.3(~{FAULT}) ; port USB_OTG_FS_OVCR
USB_OTG_FS_P: U30.3(IO_2) ; port USB_OTG_FS_P
USB_OTG_FS_PWR_EN: R188.1 U29.4(EN) ; port USB_OTG_FS_PWR_EN
USB_OTG_FS_VBUS: C85.2 CN27.1(VBUS) R182.1 R189.1 U29.1(OUT) U33.1(IO1) ; port USB_OTG_FS_VBUS
NetCN27_2: CN27.2(DM) U30.6(IO1)
NetCN27_3: CN27.3(DP) U30.4(IO2)
NetLD10_1: LD10.1 R195.1
NetLD11_1: LD11.1 R196.1
NetLD11_2: LD11.2 T1.3(C)
NetR189_2: R189.2 R191.2 T1.1(B)

Not connected (* = marked no-connect by the designer): U30 5(VBUS)*

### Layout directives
differential pair: USB_OTG_FS_N, USB_OTG_FS_P

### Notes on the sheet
- USB_OTG_FS
- (Always ON)
- VBUS OK LED
- Curr=5mA, Lum=25%
- From MFX
- MFX7
- VBUS OVRCR LED
- Curr=4mA, Lum=25%
- PA9
- PB7
- PA11
- PA12
- PA10
- LIMITATIONS (see MCU page) :
- ESD protections should be near connector
- CAN (PA11/PA12) (jumper)

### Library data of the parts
C85 = MCD-00009: as C72 on sheet STLink_V3E_SWD
CN27 = MCD-00661: USB-MICRO-AB Receptacle, RA, SMT + DIP, Standard, Top Mount, USB certified (symbol & footprint compatible with MCD-00022); Part_Type: Connector; Manufacturer_Part_Number: ZX62RD-AB-5P8(30); Manufacturer: HIROSE; Part_Preference: Recommended; Provided_By: SUBCO; Component_Country_Of_Origin: Japan; ID: 3083; Order_Code_RS: 136-1404; ShowFields: YES
LD10 = MCD-00587: as LD8 on sheet STLink_V3E_SWD
LD11 = MCD-00588: LED Green, 0603 SMD, Forward Voltage Typ=2V, Max=2.5V; Part_Type: Display; Manufacturer_Part_Number: LG Q396-PS-35; Manufacturer: OSRAM OPTO SEMICONDUCTORS; Alternate_Manufacturer_Part_Number: VLMTG1300-GS08; Alternate_Manufacturer: VISHAY SEMICONDUCTOR OPTO DIVISION; Part_Preference: Recommended; Partial_Alternate_Internal_Part_Number: MCD-02400, MCD-03155; Provided_By: SUBCO; Component_Country_Of_Origin: Unknown; ID: 3155; ShowFields: YES
R182 = MCD-00179: Resistor,0R,0805,5%; Manufacturer_Part_Number: RC0805JR-070RL; Manufacturer: YAGEO; Part_Preference: Recommended; Provided_By: SUBCO; ECCN_US: EAR99; ECCN_EU: NEC; Component_Country_Of_Origin: China; ID: 2685; ShowFields: YES
R188 R191 = MCD-00053: as R144 on sheet STLink_V3E_SWD
R189 R193 = MCD-00063: Resistor,47K,0402,1%,1/16W; Manufacturer_Part_Number: RC0402FR-0747KL; Manufacturer: YAGEO; Part_Preference: Recommended; Provided_By: SUBCO; ECCN_US: EAR99; ECCN_EU: NEC; Component_Country_Of_Origin: China; ID: 2528; Order_Code_RS: 9239430; ShowFields: YES
R195 = MCD-00461: Resistor,360R,0402,1%,1/16W; Manufacturer_Part_Number: RC0402FR-07360RL; Manufacturer: YAGEO; Part_Preference: Recommended; Provided_By: SUBCO; ECCN_US: EAR99; ECCN_EU: NEC; Component_Country_Of_Origin: China; ID: 2816; ShowFields: YES
R196 = MCD-00441: Resistor,270R,0402,1%,1/16W; Manufacturer_Part_Number: RC0402FR-07270RL; Manufacturer: YAGEO; Part_Preference: Recommended; Provided_By: SUBCO; ECCN_US: EAR99; ECCN_EU: NEC; Component_Country_Of_Origin: China; ID: 2838; ShowFields: YES
T1 = MCD-00073: NPN Bipolar Transistor; Manufacturer_Part_Number: BSR14; Manufacturer: ON SEMICONDUCTOR; Part_Type: IC; Alternate_Manufacturer_Part_Number: MMBT2222LT1G / MMBT2222ALT1G / MMBT2222ALT3G; Part_Preference: Recommended; Partial_Alternate_Internal_Part_Number: MCD-01737, MCD-03305, , MCD-02988; Provided_By: SUBCO; ECCN_US: EAR99; ECCN_EU: NEC; Component_Country_Of_Origin: Unknown; ID: 2519; ShowFields: YES
U29 = MCD-00159: 500mA, Enhanced single channel power switches with active high enable pin; Manufacturer: STMICROELECTRONICS; Part_Type: IC; Alternate_Manufacturer_Part_Number: TPS2051C; Alternate_Manufacturer: TEXAS INSTRUMENTS; BMS_Part_Number: 9159009; Part_Preference: Recommended; Provided_By: SUBCO with ST control; ECCN_US: EAR99; ECCN_EU: NEC; Component_Country_Of_Origin: Malaysia; ID: 2708; Order_Code_RS: 165-5516; ShowFields: YES
U30 = MCD-00163: Very low capacitance ESD protection; Part_Type: Diode; Manufacturer: STMICROELECTRONICS; BMS_Part_Number: 9151075; Part_Preference: Recommended; Provided_By: SUBCO with ST control; ECCN_US: EAR99; ECCN_EU: NEC; Component_Country_Of_Origin: China; ID: 2707; Order_Code_RS: 920-6266; ShowFields: YES
U33 = MCD-00251: as U23 on sheet STLink_V3E_SWD
U34 = MCD-00170: ESD protection 6V1; Part_Type: Diode; Manufacturer: STMICROELECTRONICS; BMS_Part_Number: 9151132; Manufacturer_HQ_COO: EU; Part_Preference: Recommended; Provided_By: SUBCO with ST control; ECCN_US: EAR99; ECCN_EU: NEC; Component_Country_Of_Origin: China; ID: 2696; Order_Code_RS: 795-8404; ShowFields: YES

## Sheet USB_OTG_HS_externalPHY.SchDoc: USB OTG HS with external PHY
size A4; Date: Not used; ApprovedBy: Not used; CheckedBy: Not used; Author: Not used; CompanyName: STMicroelectronics; DrawnBy: Not used; Engineer: Not used; Organization: Not used; Address1: Not used; Address2: Not used; Address3: Not used; Address4: Not used; DocumentNumber: Not used; Revision: Not used; SheetNumber: 6; SheetTotal: 23
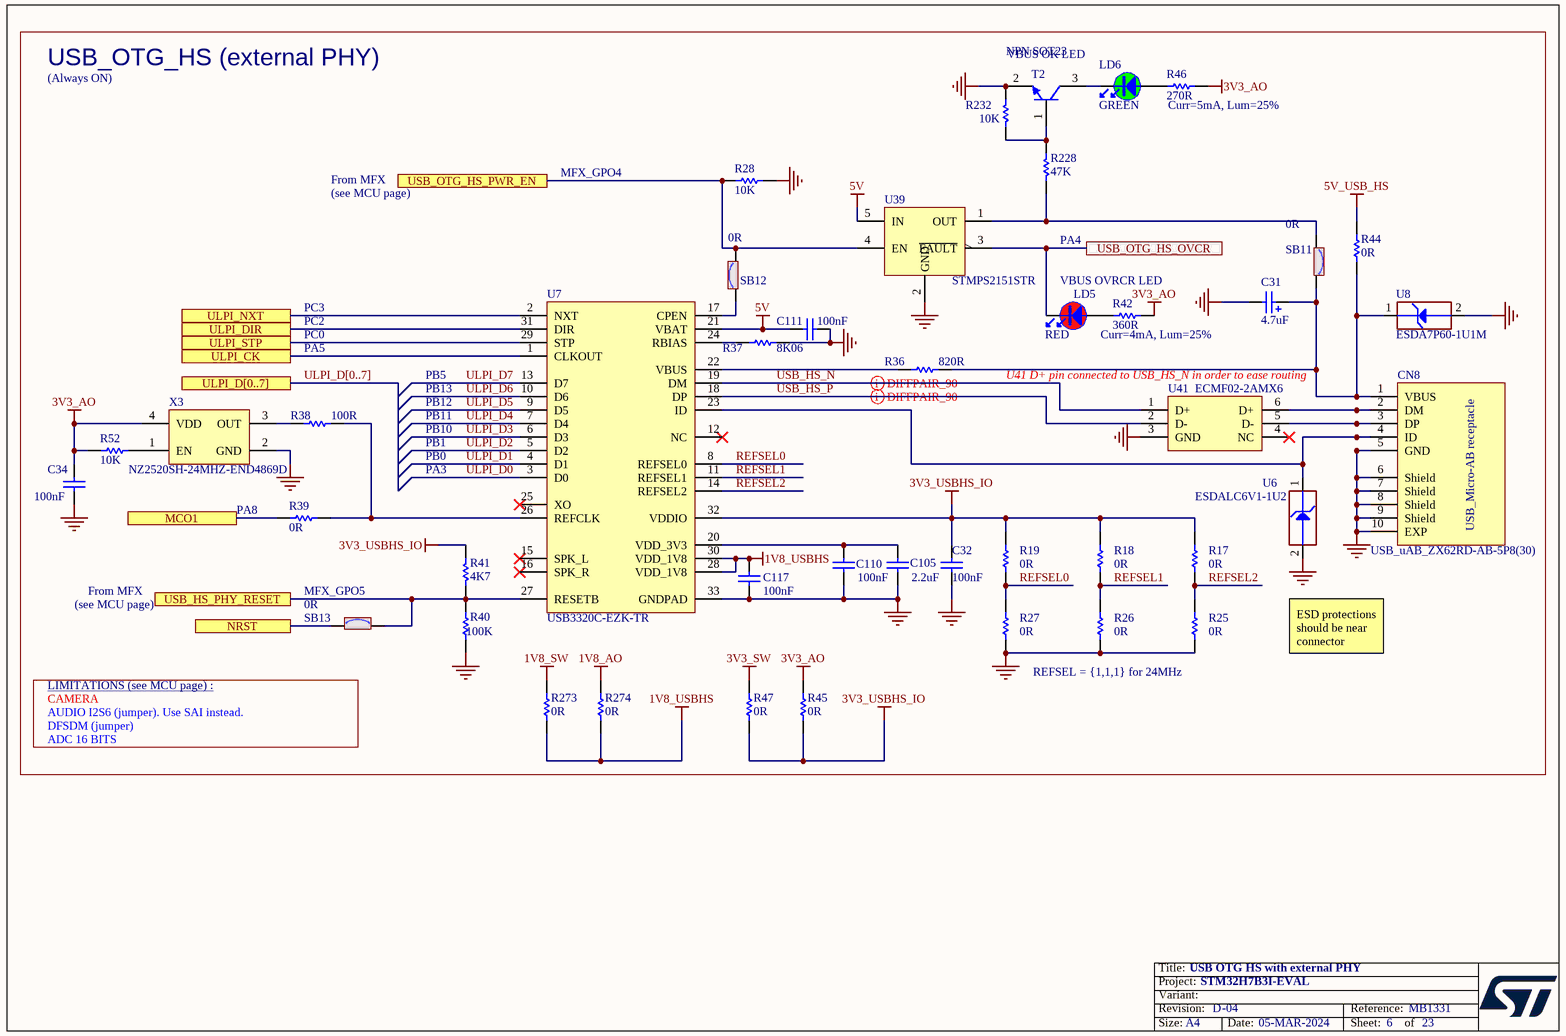
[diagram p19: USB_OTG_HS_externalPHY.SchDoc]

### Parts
C31  value 4.7uF  [CPOL_TAJ-A_1206_H180]  (hidden comment: Cap_POL_TANA)
C32  value 100nF  [C0402]  (hidden comment: Capacitor)
C34  value 100nF  [C0402]  (hidden comment: Capacitor)
C105  value 2.2uF  [C0603]  (hidden comment: Capacitor)
C110  value 100nF  [C0402]  (hidden comment: Capacitor)
C111  value 100nF  [C0402]  (hidden comment: Capacitor)
C117  value 100nF  [C0402]  (hidden comment: Capacitor)
CN8  value USB_uAB_ZX62RD-AB-5P8(30)  [CON_USBMICROAB_MOLEX_47590-0001_H3]  (hidden comment: USB_uAB_47590.0001)
LD5  value RED  [LED_0603_VISHAY_VLMS1300-GS08_RED_1A2K_H0P8]  (hidden comment: LED_red)
LD6  value GREEN  [LED_0603_OSRAM_LG-Q396-PS-35_GREEN_1A2K_H0P4]  (hidden comment: LED_green)
R17  value 0R  [R0603]  (hidden comment: Resistor)
R18  value 0R  [R0603]  (hidden comment: Resistor)
R19  value 0R  [R0603]  (hidden comment: Resistor)
R25  value 0R  [R0603]  (hidden comment: Resistor)
R26  value 0R  [R0603]  (hidden comment: Resistor)
R27  value 0R  [R0603]  (hidden comment: Resistor)
R28  value 10K  [R0402]  (hidden comment: Resistor)
R36  value 820R  [R0603]  (hidden comment: Resistor)
R37  value 8K06  [R0603]  (hidden comment: Resistor)
R38  value 100R  [R0402]  (hidden comment: Resistor)
R39  value 0R  [R0402]  (hidden comment: Resistor)
R40  value 100K  [R0402]  (hidden comment: Resistor)
R41  value 4K7  [R0402]  (hidden comment: Resistor)
R42  value 360R  [R0402]  (hidden comment: Resistor)
R44  value 0R  [R0805]  (hidden comment: Resistor)
R45  value 0R  [R0603]  (hidden comment: Resistor)
R46  value 270R  [R0402]  (hidden comment: Resistor)
R47  value 0R  [R0603]  (hidden comment: Resistor)
R52  value 10K  [R0402]  (hidden comment: Resistor)
R228  value 47K  [R0402]  (hidden comment: Resistor)
R232  value 10K  [R0402]  (hidden comment: Resistor)
R273  value 0R  [R0603]  (hidden comment: Resistor)
R274  value 0R  [R0603]  (hidden comment: Resistor)
SB11  value 0R  [SOLDER-BRIDGE_R0603-0R]  (hidden comment: SB_ON)
SB12  value 0R  [SOLDER-BRIDGE_R0603-0R]  (hidden comment: SB_ON)
SB13  value 0R  [SOLDER-BRIDGE_R0603-0R]  (hidden comment: SB_ON)
T2  value NPN SOT23  [NPN_SOT23]  (hidden comment: 9013-SOT23)
U6  value ESDALC6V1-1U2  [ESD_ST0201]  (hidden comment: ESD-TRANSIL)
U7  value USB3320C-EZK-TR  [ICC_QFN32-EPAD_5X5_P050]  (hidden comment: USB3320C-EZK)
U8  value ESDA7P60-1U1M  [ESD_QFN2_1P6X1_P125]  (hidden comment: ESD-TRANSIL)
U39  STMPS2151STR  [MOS_SOT23-5L]
U41  ECMF02-2AMX6  [ESD_QFN-6L_1P7X1P5_P050]
X3  Manufacturer_Part_Number: NZ2520SH-24MHZ-END4869D  [OSC_NDK_NZ2520SB_4P]  (hidden comment: OSCILLATOR_4_PINS)

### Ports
MCO1, NRST, ULPI_CK, ULPI_D[0..7], ULPI_DIR, ULPI_NXT, ULPI_STP, USB_HS_PHY_RESET, USB_OTG_HS_OVCR, USB_OTG_HS_PWR_EN

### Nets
1V8_AO: R274.1
1V8_SW: R273.1
1V8_USBHS: C117.1 R273.2 R274.2 U7.28(VDD_1V8) U7.30(VDD_1V8)
3V3_AO: C34.2 R42.2 R45.1 R46.2 R52.1 X3.4(VDD)
3V3_SW: R47.1
3V3_USBHS_IO: C32.2 R17.2 R18.2 R19.2 R41.2 R45.2 R47.2 U7.32(VDDIO)
5V: C111.1 U7.21(VBAT) U39.5(IN)
5V_USB_HS: R44.2
GND: C31.2 C32.1 C34.1 C105.1 C110.2 C111.2 C117.2 CN8.5(GND) CN8.6(Shield) CN8.7(Shield) CN8.8(Shield) CN8.9(Shield) CN8.10(EXP) R25.1 R26.1 R27.1 R28.2 R37.2 R40.1 R232.1 T2.2(E) U6.2(GND) U7.33(GNDPAD) U8.2(GND) U39.2(GND) U41.3(GND) X3.2(GND)
MCO1: R39.1 ; port MCO1
NRST: SB13.2 ; port NRST
REFSEL0: R19.1 R27.2 U7.8(REFSEL0)
REFSEL1: R18.1 R26.2 U7.11(REFSEL1)
REFSEL2: R17.1 R25.2 U7.14(REFSEL2)
ULPI_CK: U7.1(CLKOUT) ; port ULPI_CK
ULPI_D0: U7.3(D0)
ULPI_D1: U7.4(D1)
ULPI_D2: U7.5(D2)
ULPI_D3: U7.6(D3)
ULPI_D4: U7.7(D4)
ULPI_D5: U7.9(D5)
ULPI_D6: U7.10(D6)
ULPI_D7: U7.13(D7)
ULPI_DIR: U7.31(DIR) ; port ULPI_DIR
ULPI_NXT: U7.2(NXT) ; port ULPI_NXT
ULPI_STP: U7.29(STP) ; port ULPI_STP
USB_HS_N: U7.19(DM) U41.1(D+)
USB_HS_P: U7.18(DP) U41.2(D-)
USB_HS_PHY_RESET: R40.2 R41.1 SB13.1 U7.27(RESETB) ; port USB_HS_PHY_RESET
USB_OTG_HS_OVCR: LD5.2 U39.3(~{FAULT}) ; port USB_OTG_HS_OVCR
USB_OTG_HS_PWR_EN: R28.1 SB12.1 U39.4(EN) ; port USB_OTG_HS_PWR_EN
NetC31_1: C31.1 CN8.1(VBUS) R36.2 R44.1 SB11.2 U8.1(IO1)
NetC105_2: C105.2 C110.1 U7.20(VDD_3V3)
NetCN8_2: CN8.2(DM) U41.6(D+)
NetCN8_3: CN8.3(DP) U41.5(D-)
NetCN8_4: CN8.4(ID) U6.1(IO1) U7.23(ID)
NetLD5_1: LD5.1 R42.1
NetLD6_1: LD6.1 R46.1
NetLD6_2: LD6.2 T2.3(C)
NetR36_1: R36.1 U7.22(VBUS)
NetR37_1: R37.1 U7.24(RBIAS)
NetR38_1: R38.1 X3.3(OUT)
NetR38_2: R38.2 R39.2 U7.26(REFCLK)
NetR52_2: R52.2 X3.1(EN)
NetR228_1: R228.1 SB11.1 U39.1(OUT)
NetR228_2: R228.2 R232.2 T2.1(B)
NetSB12_2: SB12.2 U7.17(CPEN)

Not connected (* = marked no-connect by the designer): U7 12(NC)* 15(SPK_L)* 16(SPK_R)* 25(XO)*; U41 4(NC)*

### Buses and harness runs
bus ULPI_D[0..7] = port ULPI_D[0..7]

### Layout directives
differential pair: USB_HS_N, USB_HS_P

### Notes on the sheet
- VBUS OK LED
- USB_OTG_HS (external PHY)
- (Always ON)
- (near R46) Curr=5mA, Lum=25%
- MFX_GPO4
- From MFX
- (see MCU page)
- PA4
- PC3
- VBUS OVRCR LED
- PC2
- PC0
- PA5
- PB5
- (near U41) U41 D+ pin connected to USB_HS_N in order to ease routing
- Curr=4mA, Lum=25%
- PB1
- PB10
- PB11
- PB12
- PB13
- PA8
- PA3
- PB0
- (near SB13) MFX_GPO5
- ESD protections should be near connector
- LIMITATIONS (see MCU page) :
- AUDIO I2S6 (jumper). Use SAI instead.
- CAMERA
- REFSEL = {1,1,1} for 24MHz
- DFSDM (jumper)
- ADC 16 BITS

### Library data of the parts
C31 = MCD-00007: Capacitor, Tantalum, 4.7uF, 16V, 10%, 4ohms, pkg Type_A (3216 metric), T=1.6mm; Manufacturer_Part_Number: TAJA475K016R; Manufacturer: AVX; Part_Preference: Recommended; Partial_Alternate_Internal_Part_Number: MCD-03149; Provided_By: SUBCO; ECCN_US: EAR99; ECCN_EU: NEC; Component_Country_Of_Origin: El Salvador; ID: 2473; Order_Code_RS: 197269; ShowFields: YES
C32 C34 C110 C111 C117 = MCD-00006: as C64 on sheet STLink_V3E_SWD
C105 = MCD-00012: as C77 on sheet STLink_V3E_SWD
CN8 = MCD-00661: as CN27 on sheet USB_OTG_FS
LD5 = MCD-00587: as LD8 on sheet STLink_V3E_SWD
LD6 = MCD-00588: as LD11 on sheet USB_OTG_FS
R17-R19 R25-R27 R45 R47 R273 R274 = MCD-00056: Resistor,0R,0603,5%,1/10W; Manufacturer_Part_Number: RC0603JR-070RL; Manufacturer: YAGEO; Part_Preference: Recommended; Provided_By: SUBCO; ECCN_US: EAR99; ECCN_EU: NEC; Component_Country_Of_Origin: China; ID: 2536; Order_Code_RS: 9233130RL; ShowFields: YES
R28 R52 R232 = MCD-00053: as R144 on sheet STLink_V3E_SWD
R36 = MCD-00528: as R225 on sheet ExtensionConnector
R37 = MCD-00570: Resistor,8K06,0603,1%,1/10W; Manufacturer_Part_Number: RC0603FR-078K06L; Manufacturer: YAGEO; Part_Preference: Recommended; Provided_By: SUBCO; ECCN_US: EAR99; ECCN_EU: NEC; Component_Country_Of_Origin: China; ID: 3177; ShowFields: YES
R38 = MCD-00067: as R145 on sheet STLink_V3E_SWD
R39 = MCD-00052: as R398 on sheet STLink_V3E_SWD
R40 = MCD-00059: as R150 on sheet STLink_V3E_SWD
R41 = MCD-00065: as R146 on sheet STLink_V3E_SWD
R42 = MCD-00461: as R195 on sheet USB_OTG_FS
R44 = MCD-00179: as R182 on sheet USB_OTG_FS
R46 = MCD-00441: as R196 on sheet USB_OTG_FS
R228 = MCD-00063: as R189 on sheet USB_OTG_FS
SB11-SB13 = MCD-00071: as SB6-SB9 on sheet ExtensionConnector
T2 = MCD-00073: as T1 on sheet USB_OTG_FS
U6 = MCD-00170: as U34 on sheet USB_OTG_FS
U7 = MCD-00569: USB3320C,  Hi-Speed USB Host, Device or OTG PHY with ULPI Low Pin Interface; Manufacturer: MICROCHIP; Part_Type: IC; Part_Preference: Recommended; Provided_By: SUBCO; ECCN_US: EAR99; ECCN_EU: NEC; Component_Country_Of_Origin: Unknown; ID: 3179; Order_Code_RS: 889-5840; ShowFields: YES
U8 = MCD-00251: as U23 on sheet STLink_V3E_SWD
U39 = MCD-00159: as U29 on sheet USB_OTG_FS
U41 = MCD-00649: as U26 on sheet STLink_V3E_SWD
X3 = MCD-01976: Oscillator, SPXO, 24MHz, +/-50ppm, square wave, 3V3, 2.5x2mm; Part_Type: Crystal_Osc; Manufacturer: NDK; Part_Preference: Recommended; Component_Country_Of_Origin: Unknown; ShowFields: YES; ID: 4076

## Sheet FDCAN&RS232.SchDoc: FDCAN & OCSPI
size A4; Date: Not used; ApprovedBy: Not used; CheckedBy: Not used; Author: Not used; CompanyName: STMicroelectronics; DrawnBy: Not used; Engineer: Not used; Organization: Not used; Address1: Not used; Address2: Not used; Address3: Not used; Address4: Not used; DocumentNumber: Not used; Revision: Not used; SheetNumber: 15; SheetTotal: 23
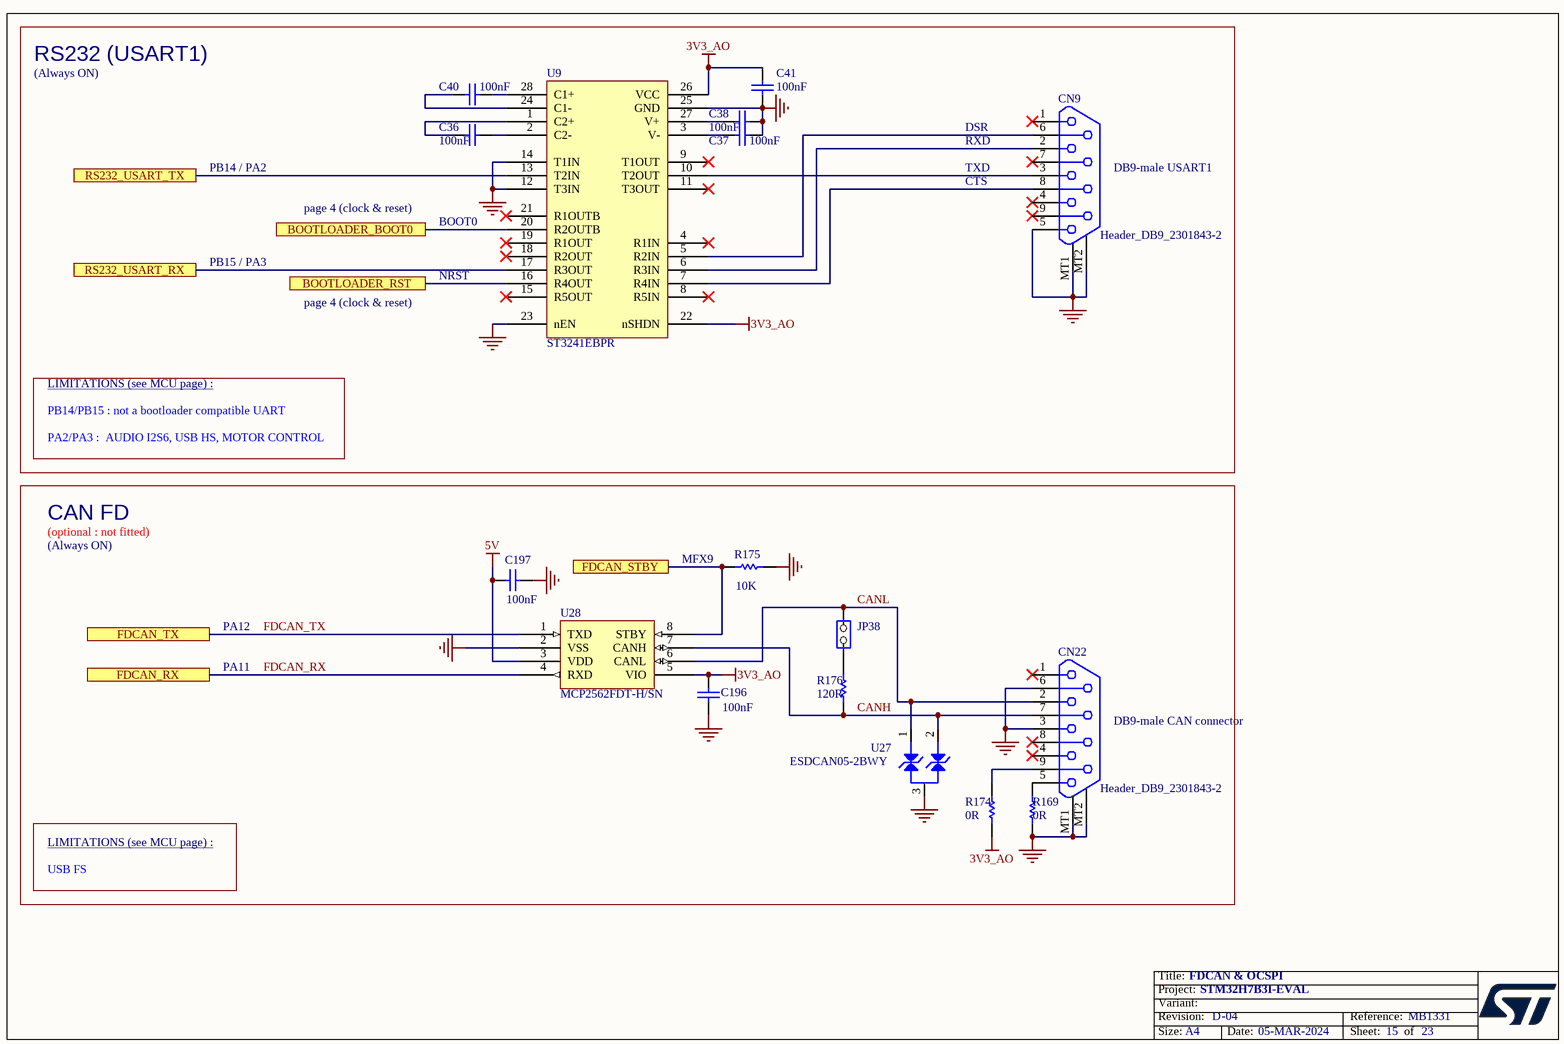
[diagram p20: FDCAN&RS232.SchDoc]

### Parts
C36  value 100nF  [C0402]  (hidden comment: Capacitor)
C37  value 100nF  [C0402]  (hidden comment: Capacitor)
C38  value 100nF  [C0402]  (hidden comment: Capacitor)
C40  value 100nF  [C0402]  (hidden comment: Capacitor)
C41  value 100nF  [C0402]  (hidden comment: Capacitor)
C196  value 100nF  [C0402]  (hidden comment: Capacitor)
C197  value 100nF  [C0402]  (hidden comment: Capacitor)
CN9  value Header_DB9_2301843-2  [CON_DB9-MALE_TYCO_2301843-2]  (hidden comment: DB9_Header_male_2301843-2)
CN22  value Header_DB9_2301843-2  [CON_DB9-MALE_TYCO_2301843-2]  (hidden comment: DB9_Header_male_2301843-2)
JP38  Jumper_Header 2x1  [CON_SAMTEC_TSW-102-07-G-S]  (value not drawn)
R169  value 0R  [R0603]  (hidden comment: Resistor)
R174  value 0R  [R0603]  (hidden comment: Resistor)
R175  value 10K  [R0402]  (hidden comment: Resistor)
R176  value 120R  [R0402]  (hidden comment: Resistor)
U9  ST3241EBPR  [ICC_SSOP28_10P2X5P3_P065]
U27  value ESDCAN05-2BWY  [DIO_SOT323]  (hidden comment: ESD-TRANSIL-DUAL-BIDIR)
U28  value MCP2562FDT-H/SN  [ICC_SO8_5X4_P127]  (hidden comment: MCP2562FD)

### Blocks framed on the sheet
RS232 (USART1): C36-C38 C40 C41 CN9 U9
CAN FD: C196 C197 CN22 JP38 R169 R174-R176 U27 U28

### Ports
BOOTLOADER_BOOT0, BOOTLOADER_RST, FDCAN_RX, FDCAN_STBY, FDCAN_TX, RS232_USART_RX, RS232_USART_TX

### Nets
3V3_AO: C41.1 C196.1 R174.1 U9.22(nSHDN) U9.26(VCC) U28.5(VIO)
5V: C197.1 U28.3(VDD)
GND: C37.1 C38.1 C41.2 C196.2 C197.2 CN9.5 CN9.MT1 CN9.MT2 CN22.3 CN22.6 CN22.MT1 CN22.MT2 R169.1 R175.2 U9.12(T3IN) U9.14(T1IN) U9.23(nEN) U9.25(GND) U27.3 U28.2(VSS)
BOOTLOADER_BOOT0: U9.20(R2OUTB) ; port BOOTLOADER_BOOT0
BOOTLOADER_RST: U9.16(R4OUT) ; port BOOTLOADER_RST
CANH: CN22.7 R176.1 U27.2 U28.7(CANH)
CANL: CN22.2 JP38.2(NO) U27.1 U28.6(CANL)
FDCAN_RX: U28.4(RXD) ; port FDCAN_RX
FDCAN_STBY: R175.1 U28.8(STBY) ; port FDCAN_STBY
FDCAN_TX: U28.1(TXD) ; port FDCAN_TX
RS232_USART_RX: U9.17(R3OUT) ; port RS232_USART_RX
RS232_USART_TX: U9.13(T2IN) ; port RS232_USART_TX
NetC36_1: C36.1 U9.1(C2+)
NetC36_2: C36.2 U9.2(C2-)
NetC37_2: C37.2 U9.3(V-)
NetC38_2: C38.2 U9.27(V+)
NetC40_1: C40.1 U9.24(C1-)
NetC40_2: C40.2 U9.28(C1+)
NetCN9_2: CN9.2 U9.6(R3IN)
NetCN9_3: CN9.3 U9.10(T2OUT)
NetCN9_6: CN9.6 U9.5(R2IN)
NetCN9_8: CN9.8 U9.7(R4IN)
NetCN22_5: CN22.5 R169.2
NetCN22_9: CN22.9 R174.2
NetJP38_1: JP38.1(COMMON) R176.2

Not connected (* = marked no-connect by the designer): CN9 1* 4* 7* 9*; CN22 1* 4* 8*; U9 4(R1IN)* 8(R5IN)* 9(T1OUT)* 11(T3OUT)* 15(R5OUT)* 18(R2OUT)* 19(R1OUT)* 21(R1OUTB)*

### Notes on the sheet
- (Always ON)
- PB14 / PA2
- RXD
- TXD
- CTS
- DSR
- (near CN9) DB9-male USART1
- page 4 (clock & reset)
- BOOT0
- PB15 / PA3
- NRST
- LIMITATIONS (see MCU page) :
- PB14/PB15 : not a bootloader compatible UART
- PA2/PA3 :  AUDIO I2S6, USB HS, MOTOR CONTROL
- (optional : not fitted)
- (near R175) MFX9
- PA12
- PA11
- (near CN22) DB9-male CAN connector
- USB FS

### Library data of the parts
C36-C38 C40 C41 C196 C197 = MCD-00006: as C64 on sheet STLink_V3E_SWD
CN9 CN22 = MCD-01978: DB9_Male, RA, TH, height 13.575mm/3.8mm; Part_Type: Connector; Manufacturer: TE CONNECTIVITY; Part_Preference: Recommended; ECCN_US: EAR99; ECCN_EU: NEC; Provided_By: SUBCO; Component_Country_Of_Origin: China; ID: 4078; ShowFields: YES
JP38 = MCD-00045: Header, 2x1, 2,54mm, VR, TH, Height 5.84mm/2.54mm; Manufacturer_Part_Number: TSW-102-07-G-S; Manufacturer: SAMTEC; Part_Type: Connector; Alternate_Manufacturer_Part_Number: 313102S111116;313102S111116; Alternate_Manufacturer: JIUBABA; LIANYI; Full_Alternate_Internal_Part_Number: MCD-02390; Part_Preference: Recommended; Partial_Alternate_Internal_Part_Number: MCD-02957, MCD-03720; Provided_By: SUBCO; Component_Country_Of_Origin: China, Costa Rica, Malaysia, USA, Vietnam; ID: 2545; Order_Code_RS: 2505044; ShowFields: YES
R169 R174 = MCD-00056: as R17-R19 on sheet USB_OTG_HS_externalPHY
R175 = MCD-00053: as R144 on sheet STLink_V3E_SWD
R176 = MCD-00194: Resistor,120R,0402,1%,1/16W; Manufacturer_Part_Number: RC0402FR-07120RL; Manufacturer: YAGEO; Part_Preference: Recommended; Provided_By: SUBCO; ECCN_US: EAR99; ECCN_EU: NEC; Component_Country_Of_Origin: China; ID: 2674; ShowFields: YES
U9 = MCD-00152: RS-232 transceiver with auto-power-down; Part_Type: IC; Manufacturer: STMICROELECTRONICS; BMS_Part_Number: 9176312; Manufacturer_HQ_COO: EU; Part_Preference: Recommended; Provided_By: SUBCO with ST control; ECCN_US: EAR99; ECCN_EU: NEC; Component_Country_Of_Origin: Philippines; ID: 2718; Order_Code_RS: 880-5383; ShowFields: YES
U27 = MCD-01358: Automotive dual-line Transil, transient voltage suppressor (TVS) for CAN bus 36V. Compliant with interfaces in automotive: CAN-FD, LIN, FlexRay, MOST, SENT, USB; Part_Type: Diode; Manufacturer: STMICROELECTRONICS; BMS_Part_Number: 9179021; Manufacturer_HQ_COO: EU; Part_Preference: Recommended; Provided_By: SUBCO with ST control; ECCN_US: EAR99; ECCN_EU: NEC; Component_Country_Of_Origin: China; ID: 3458; Order_Code_RS: 190-7635; ShowFields: YES
U28 = MCD-00129: High-Speed CAN Flexible Data Rate Transceiver; Manufacturer: MICROCHIP; Part_Type: IC; Part_Preference: Recommended; Provided_By: SUBCO; ECCN_US: EAR99; ECCN_EU: NEC; Component_Country_Of_Origin: Unknown; ID: 2737; ShowFields: YES

## Sheet STMPS2&PT100.SchDoc: STMPS2&PT100
size A4; Date: Not used; ApprovedBy: Not used; CheckedBy: Not used; Author: Not used; CompanyName: STMicroelectronics; DrawnBy: Not used; Engineer: Not used; Organization: Not used; Address1: Not used; Address2: Not used; Address3: Not used; Address4: Not used; DocumentNumber: Not used; Revision: Not used; SheetNumber: 16; SheetTotal: 23
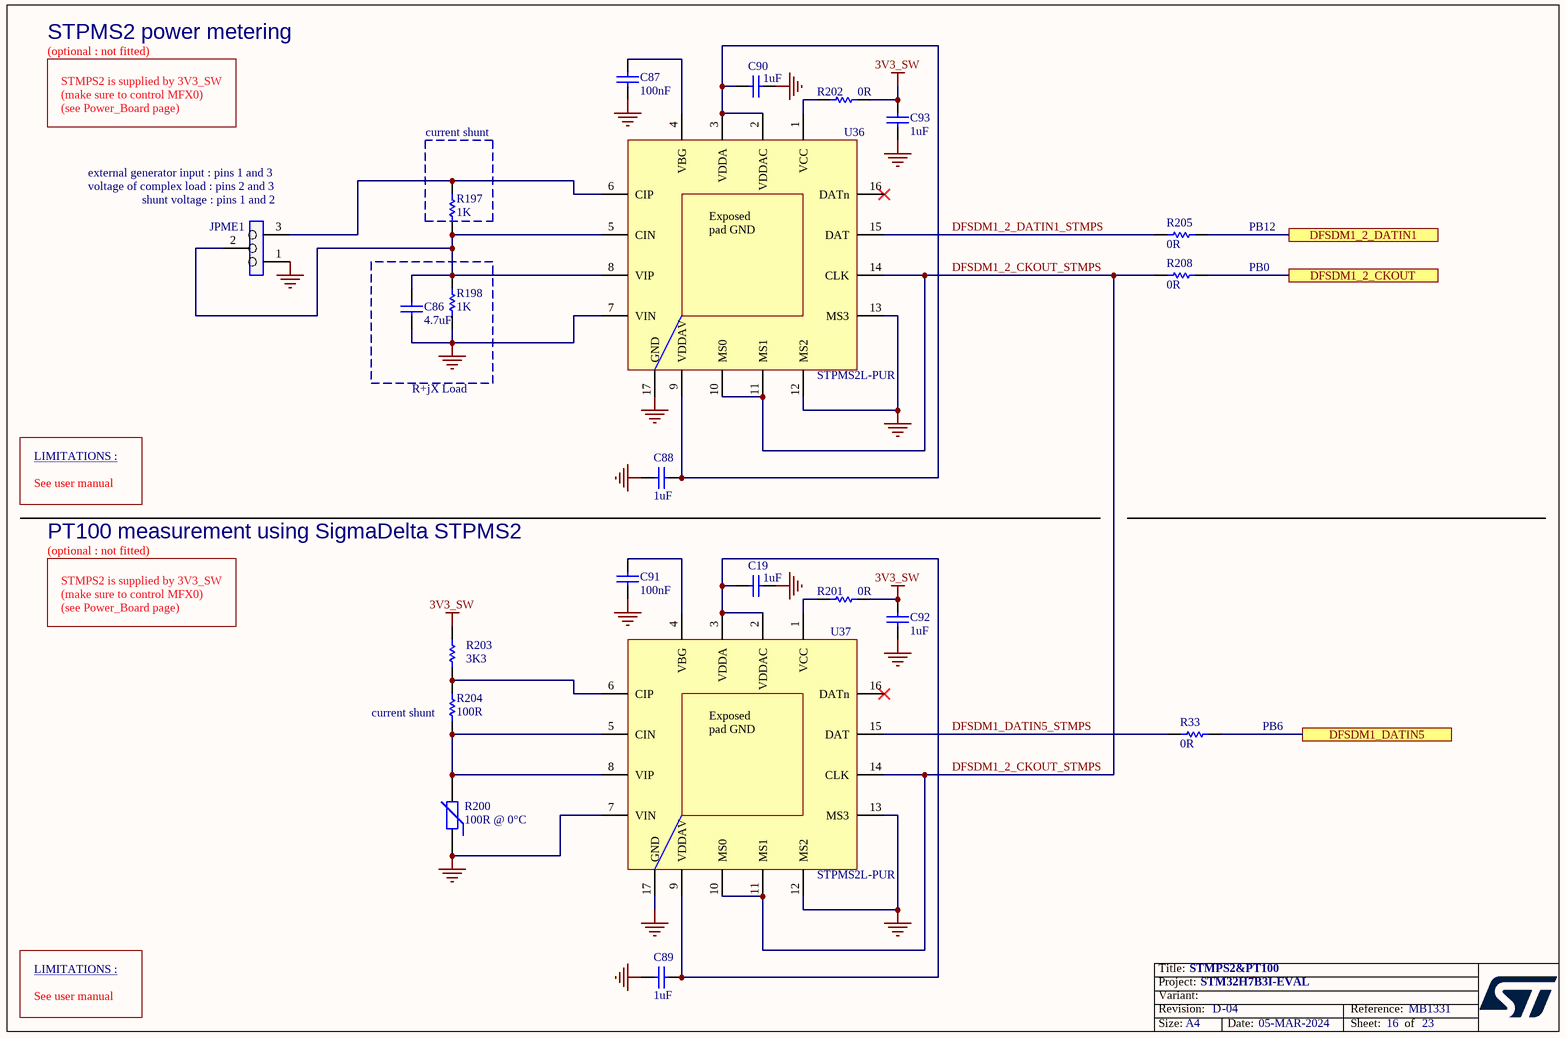
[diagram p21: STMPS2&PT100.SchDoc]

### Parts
C19  value 1uF  [C0402]  (hidden comment: Capacitor)
C86  value 4.7uF  [C0402]  (hidden comment: Capacitor)
C87  value 100nF  [C0402]  (hidden comment: Capacitor)
C88  value 1uF  [C0603]  (hidden comment: Capacitor)
C89  value 1uF  [C0603]  (hidden comment: Capacitor)
C90  value 1uF  [C0402]  (hidden comment: Capacitor)
C91  value 100nF  [C0402]  (hidden comment: Capacitor)
C92  value 1uF  [C0402]  (hidden comment: Capacitor)
C93  value 1uF  [C0402]  (hidden comment: Capacitor)
JPME1  Jumper_Header 3x1  [CON_SAMTEC_TSW-103-07-F-S]  (value not drawn)
R33  value 0R  [R0402]  (hidden comment: Resistor)
R197  value 1K  [R0603]  (hidden comment: Resistor)
R198  value 1K  [R0603]  (hidden comment: Resistor)
R200  value 100R @ 0°C  [R0603_H0P45]  (hidden comment: PT100)
R201  value 0R  [R0603]  (hidden comment: Resistor)
R202  value 0R  [R0603]  (hidden comment: Resistor)
R203  value 3K3  [R0603]  (hidden comment: Resistor)
R204  value 100R  [R0603]  (hidden comment: Resistor)
R205  value 0R  [R0402]  (hidden comment: Resistor)
R208  value 0R  [R0402]  (hidden comment: Resistor)
U36  STPMS2L-PUR  [ICC_QFN16-EPAD_4X4_P065]
U37  STPMS2L-PUR  [ICC_QFN16-EPAD_4X4_P065]

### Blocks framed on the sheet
current shunt: R197

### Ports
DFSDM1_2_CKOUT, DFSDM1_2_DATIN1, DFSDM1_DATIN5

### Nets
3V3_SW: C92.1 C93.1 R201.2 R202.2 R203.2
GND: C19.1 C86.1 C87.1 C88.1 C89.1 C90.1 C91.1 C92.2 C93.2 JPME1.1 R198.1 R200.1 U36.7(VIN) U36.12(MS2) U36.13(MS3) U36.17(GND) U37.7(VIN) U37.12(MS2) U37.13(MS3) U37.17(GND)
DFSDM1_2_CKOUT: R208.2 ; port DFSDM1_2_CKOUT
DFSDM1_2_CKOUT_STMPS: R208.1 U36.10(MS0) U36.11(MS1) U36.14(CLK) U37.10(MS0) U37.11(MS1) U37.14(CLK)
DFSDM1_2_DATIN1: R205.2 ; port DFSDM1_2_DATIN1
DFSDM1_2_DATIN1_STMPS: R205.1 U36.15(DAT)
DFSDM1_DATIN5: R33.2 ; port DFSDM1_DATIN5
DFSDM1_DATIN5_STMPS: R33.1 U37.15(DAT)
NetC19_2: C19.2 C89.2 U37.2(VDDAC) U37.3(VDDA) U37.9(VDDAV)
NetC86_2: C86.2 JPME1.2 R197.1 R198.2 U36.5(CIN) U36.8(VIP)
NetC87_2: C87.2 U36.4(VBG)
NetC88_2: C88.2 C90.2 U36.2(VDDAC) U36.3(VDDA) U36.9(VDDAV)
NetC91_2: C91.2 U37.4(VBG)
NetJPME1_3: JPME1.3 R197.2 U36.6(CIP)
NetR200_2: R200.2 R204.1 U37.5(CIN) U37.8(VIP)
NetR201_1: R201.1 U37.1(VCC)
NetR202_1: R202.1 U36.1(VCC)
NetR203_1: R203.1 R204.2 U37.6(CIP)

Not connected (* = marked no-connect by the designer): U36 16(DATn)*; U37 16(DATn)*

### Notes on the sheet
- STPMS2 power metering
- (optional : not fitted)
- STMPS2 is supplied by 3V3_SW
  (make sure to control MFX0)
  (see Power_Board page)
- external generator input : pins 1 and 3
- (near JPME1) voltage of complex load : pins 2 and 3
- (near JPME1) shunt voltage : pins 1 and 2
- PB12
- PB0
- R+jX Load
- LIMITATIONS :
- See user manual
- PT100 measurement using SigmaDelta STPMS2
- (near R204) current shunt
- PB6

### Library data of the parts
C19 C90 C92 C93 = MCD-00095: Capacitor, MLCC, 1uF, 6V3, X5R, 10%, 0402, T=0,5mm; Manufacturer_Part_Number: GRM155R61E105KA12; Manufacturer: MURATA; Alternate_Manufacturer_Part_Number: GRM155R60J105KE19; Part_Preference: Recommended; Provided_By: SUBCO; ECCN_US: EAR99; ECCN_EU: NEC; Component_Country_Of_Origin: Japan°°; ID: 2772; Order_Code_RS: 2218855; ShowFields: YES
C86 = MCD-01356: Capacitor, MLCC, 4.7uF, 6V3, X5R, 20%, 0402, T=0,5mm; Manufacturer_Part_Number: GRM155R60J475ME47; Manufacturer: MURATA; Part_Preference: Recommended; ECCN_US: EAR99; ECCN_EU: NEC; Provided_By: SUBCO; Component_Country_Of_Origin: Japan°°; ID: 3456; Order_Code_RS: 814-5230; ShowFields: YES
C87 C91 = MCD-00006: as C64 on sheet STLink_V3E_SWD
C88 C89 = MCD-00010: as C67 on sheet STLink_V3E_SWD
JPME1 = MCD-00111: Header, 3x1, 2,54mm, VR, TH, Height 5.84mm/2.54mm; Manufacturer_Part_Number: TSW-103-07-F-S; Manufacturer: SAMTEC; Part_Type: Connector; Part_Preference: Recommended; Provided_By: SUBCO; ECCN_US: EAR99; ECCN_EU: NEC; Component_Country_Of_Origin: China, Costa Rica, Malaysia, USA, Vietnam; ID: 2760; Order_Code_RS: 161-2248; ShowFields: YES
R33 R205 R208 = MCD-00052: as R398 on sheet STLink_V3E_SWD
R197 R198 = MCD-00070: Resistor,1K,0603,1%,1/10W; Manufacturer_Part_Number: RC0603FR-071KL; Manufacturer: YAGEO; Part_Preference: Recommended; Provided_By: SUBCO; ECCN_US: EAR99; ECCN_EU: NEC; Component_Country_Of_Origin: China; ID: 2522; Order_Code_RS: 9238484RL; ShowFields: YES
R200 = MCD-00680: Resistor, SMD PTS 100ohm @ 0°C Flat Chip Temperature Sensor; Manufacturer_Part_Number: PTS060301B100RP100; Manufacturer: VISHAY; Part_Preference: Recommended; Provided_By: SUBCO; ECCN_US: EAR99; ECCN_EU: NEC; Component_Country_Of_Origin: Germany; ID: 3064; Order_Code_RS: 179-3948; ShowFields: YES
R201 R202 = MCD-00056: as R17-R19 on sheet USB_OTG_HS_externalPHY
R203 = MCD-00352: Resistor,3K3,0603,1%,1/10W; Manufacturer_Part_Number: RC0603FR-073K3L; Manufacturer: YAGEO; Part_Preference: Recommended; Provided_By: SUBCO; ECCN_US: EAR99; ECCN_EU: NEC; Component_Country_Of_Origin: China; ID: 2927; ShowFields: YES
R204 = MCD-00224: Resistor,100R,0603,1%,1/10W; Manufacturer_Part_Number: RC0603FR-07100RL; Manufacturer: YAGEO; Part_Preference: Recommended; Provided_By: SUBCO; ECCN_US: EAR99; ECCN_EU: NEC; Component_Country_Of_Origin: China; ID: 2643; ShowFields: YES
U36 U37 = MCD-00681: Smart sensor II dual-channel 1-bit, 4 MHz, second-order sigmadelta modulator with embedded PGLNA; Part_Type: IC; Manufacturer: STMICROELECTRONICS; BMS_Part_Number: 9177717; Manufacturer_HQ_COO: EU; Part_Preference: Recommended; Provided_By: SUBCO with ST control; ECCN_US: EAR99; ECCN_EU: NEC; Component_Country_Of_Origin: Malaysia; ID: 3063; ShowFields: YES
